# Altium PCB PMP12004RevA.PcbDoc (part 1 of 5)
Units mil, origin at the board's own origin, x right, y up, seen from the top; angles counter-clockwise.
Board outline 5500 x 4500 mil, 6 copper layers (Top Layer, GND, Signal Layer 1, Signal Layer 2, PWR Split, Bottom Layer), stack 0 mil thick; 355 components, 130 nets, 833 pads, 904 vias.
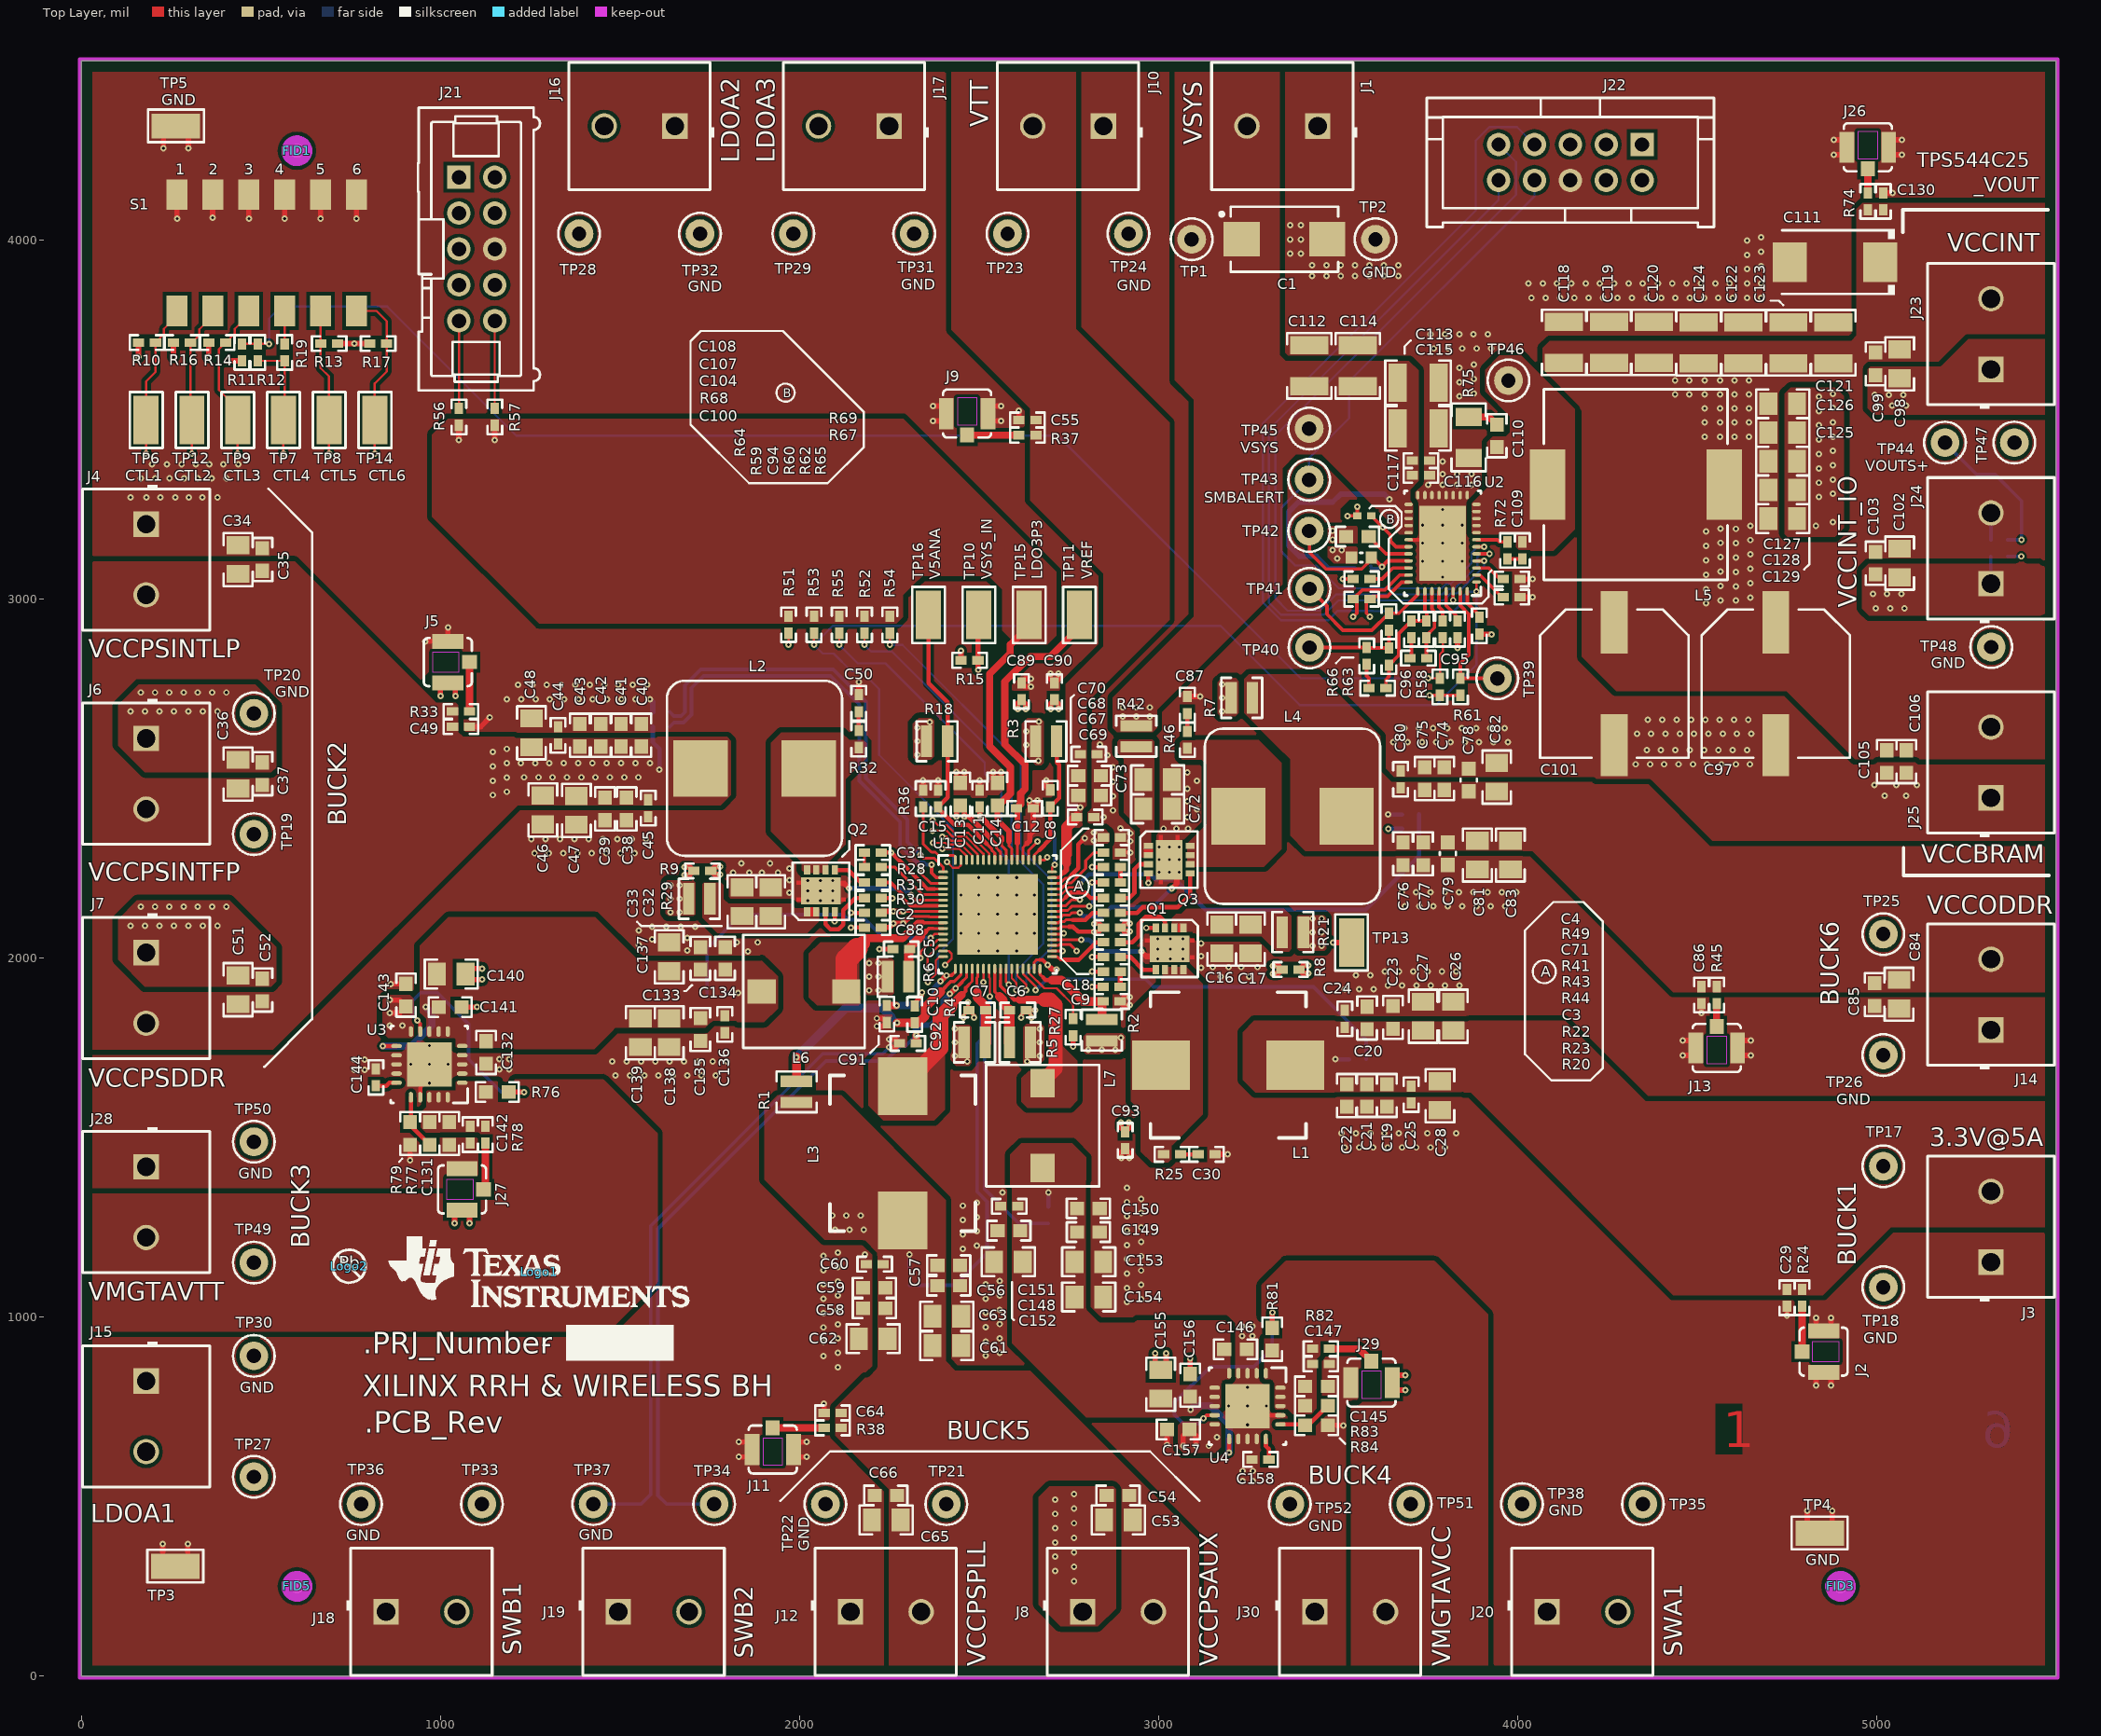
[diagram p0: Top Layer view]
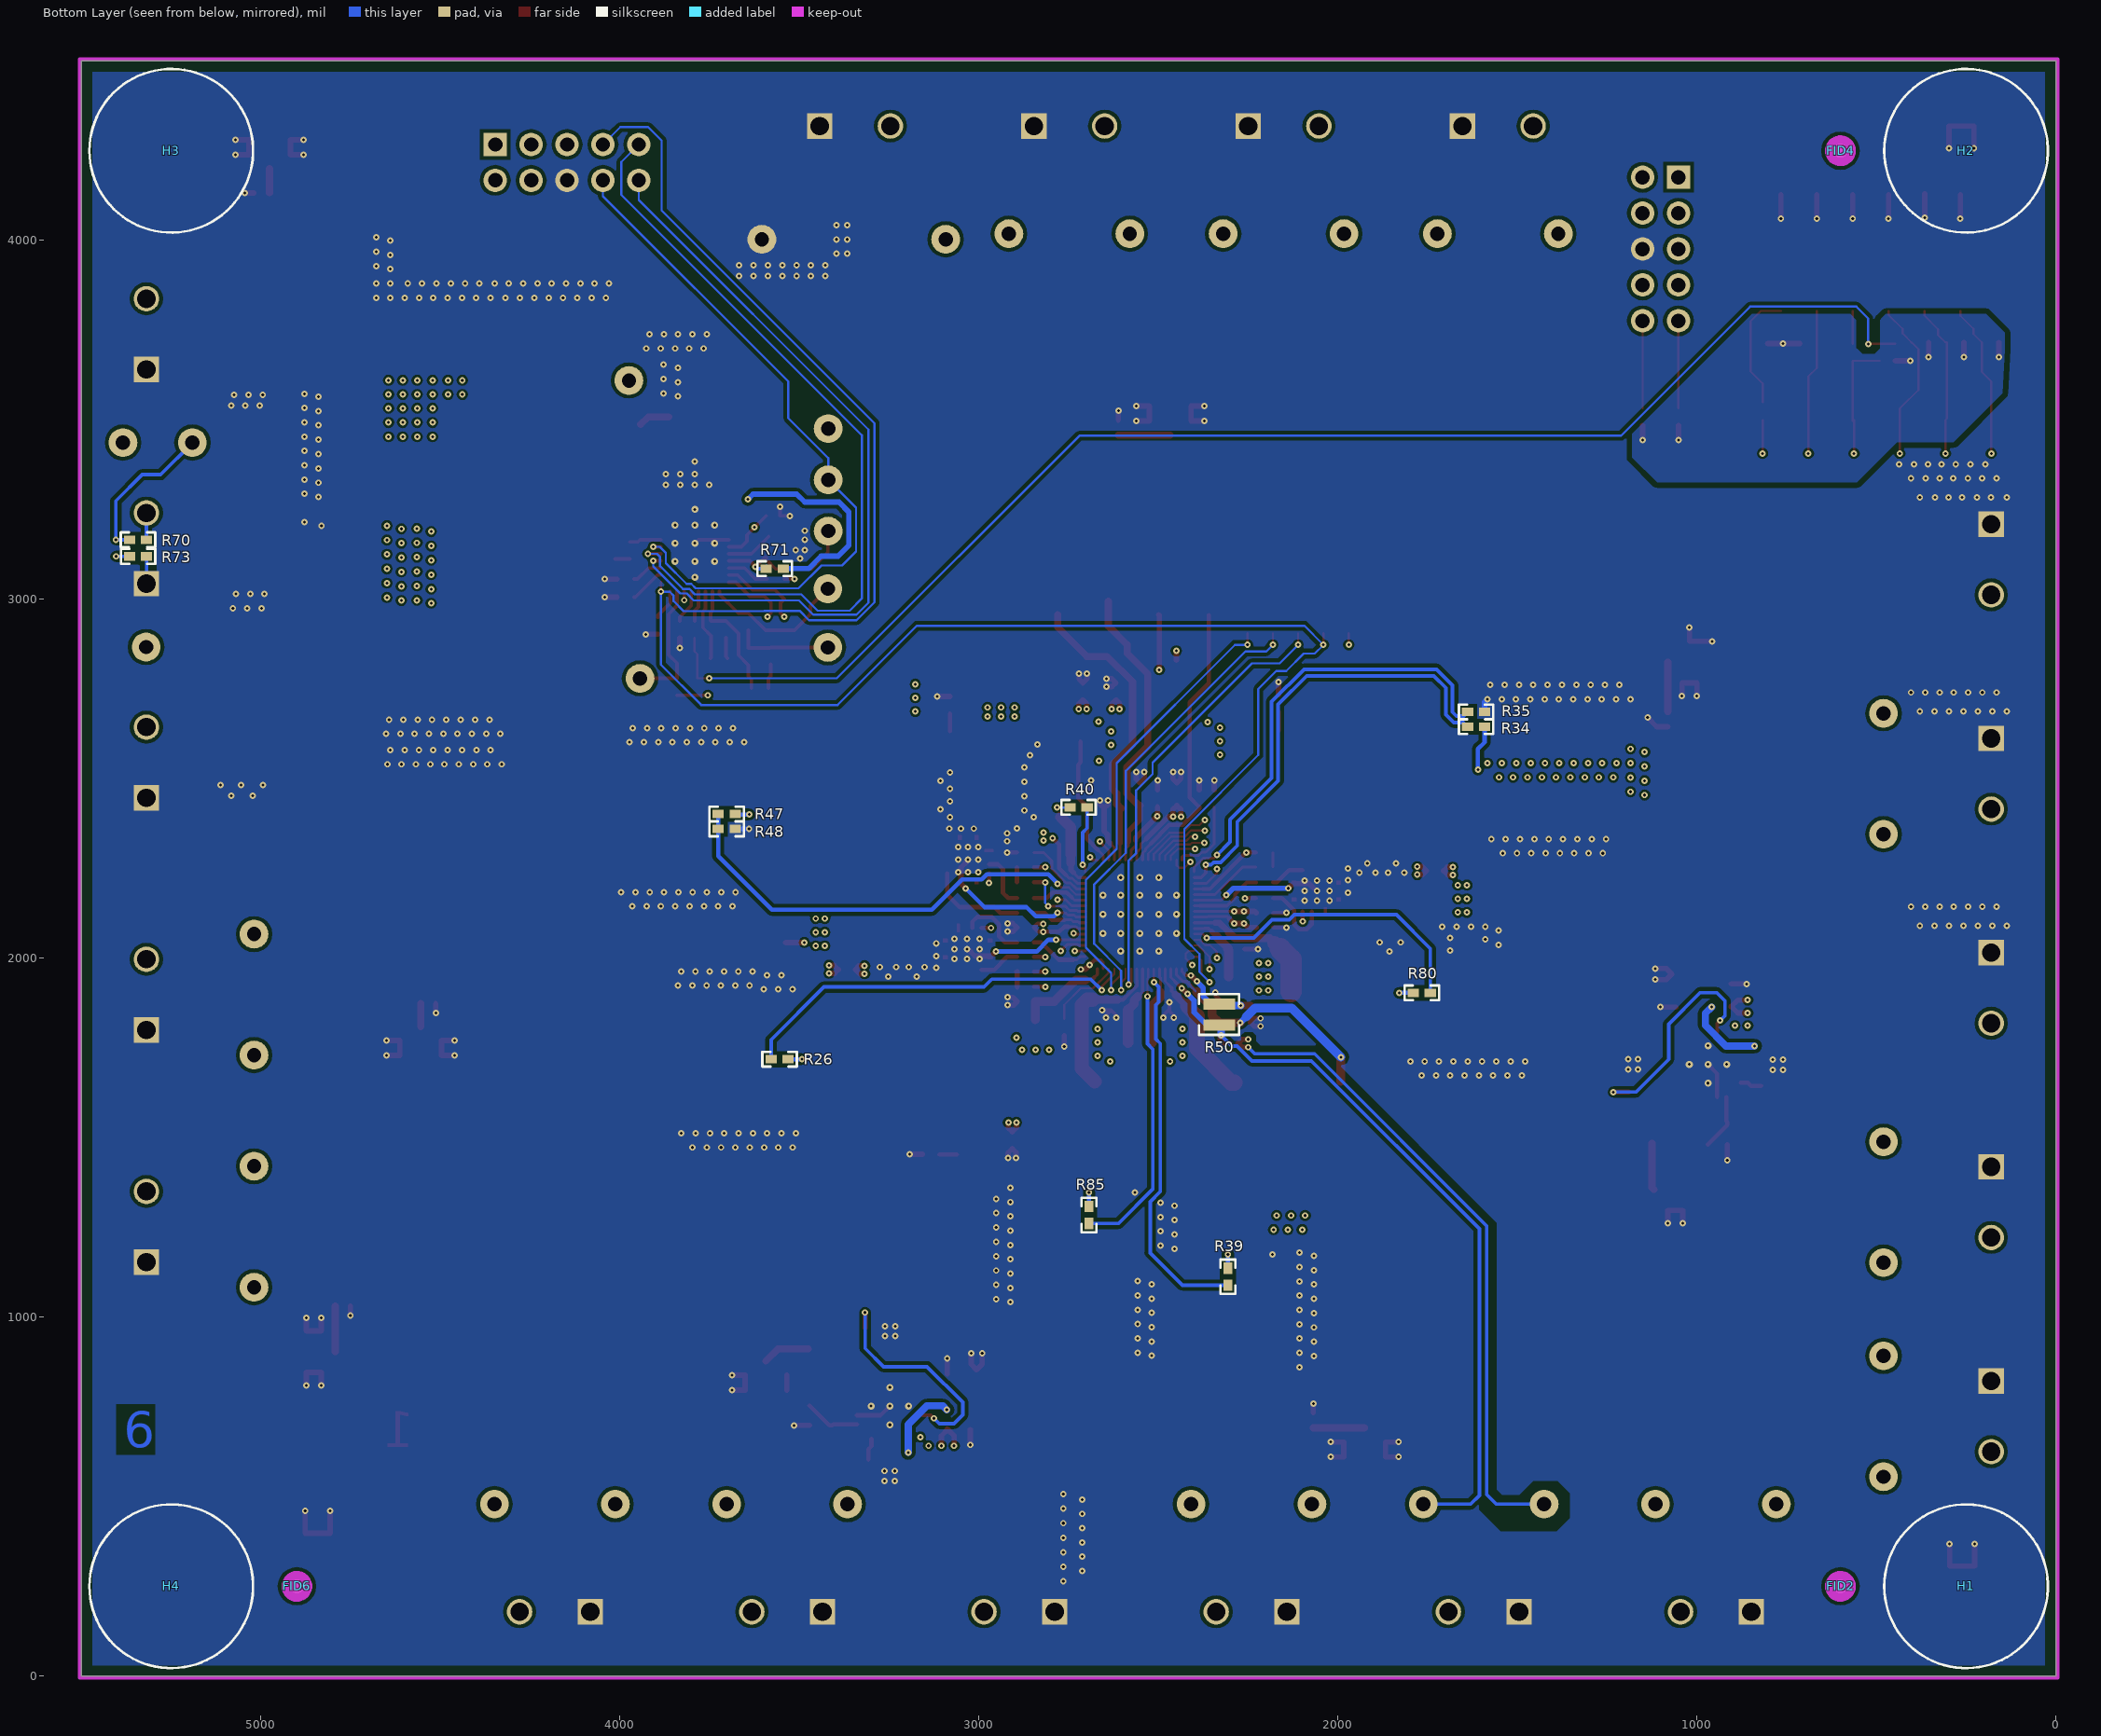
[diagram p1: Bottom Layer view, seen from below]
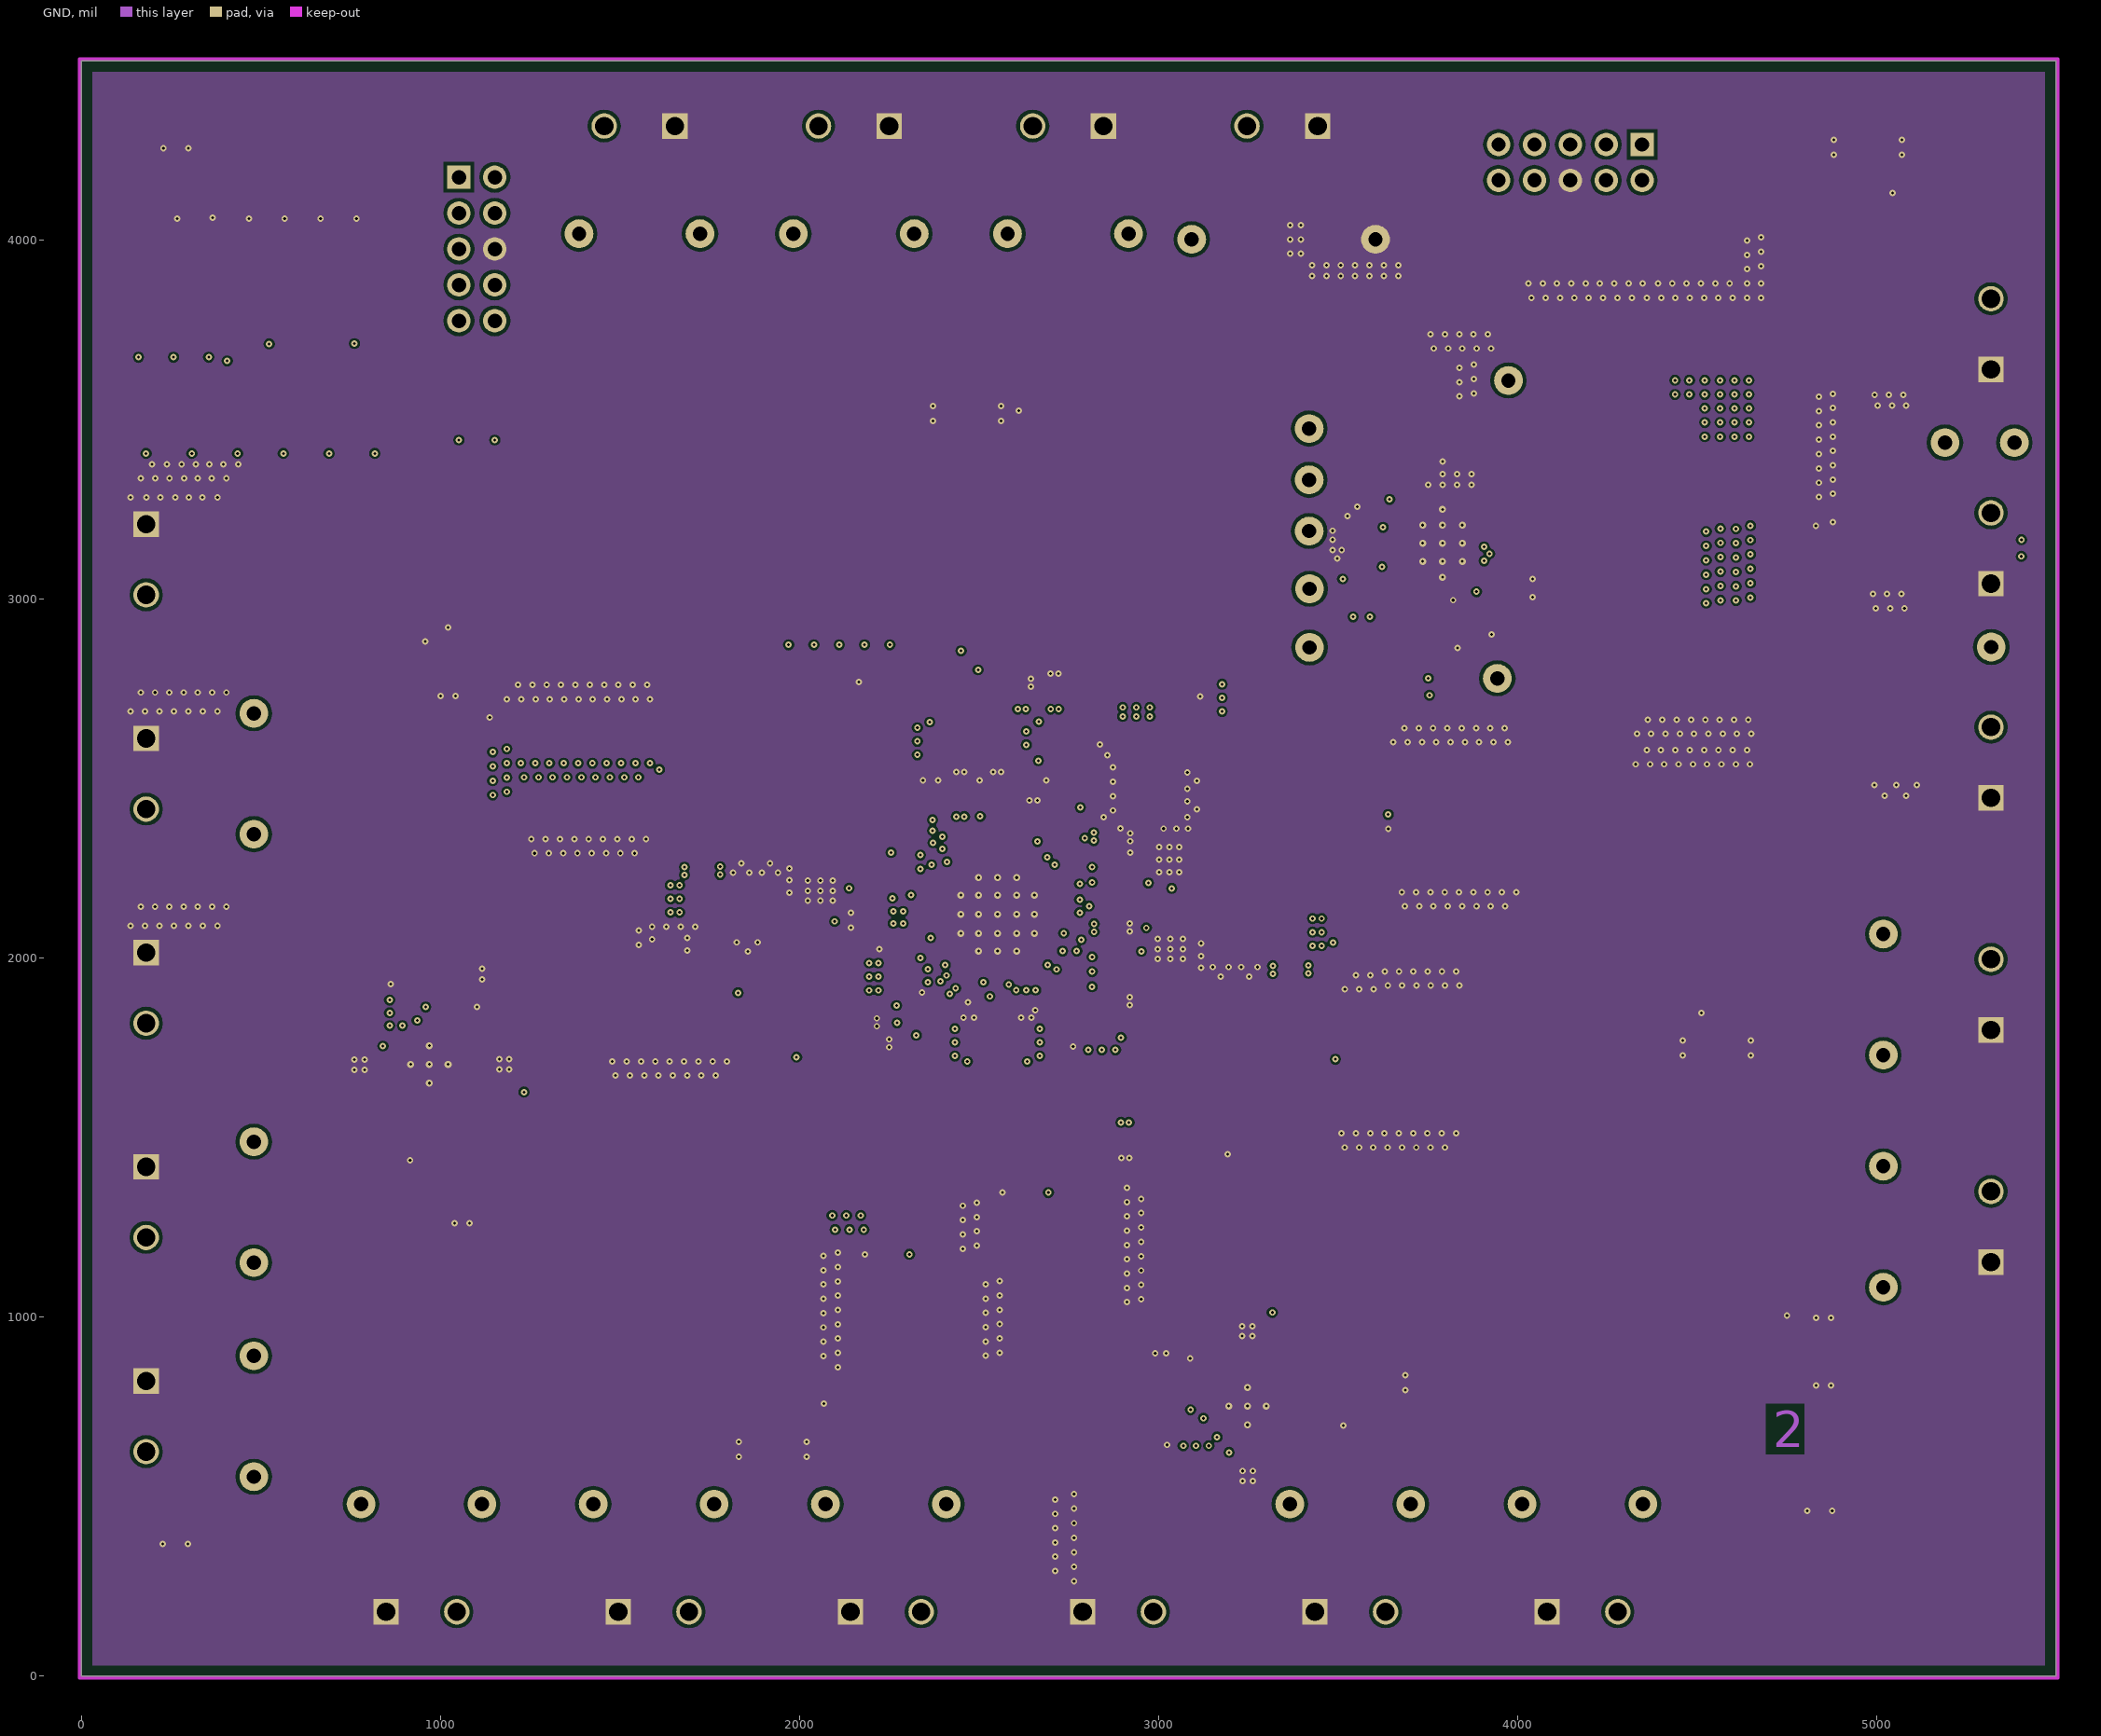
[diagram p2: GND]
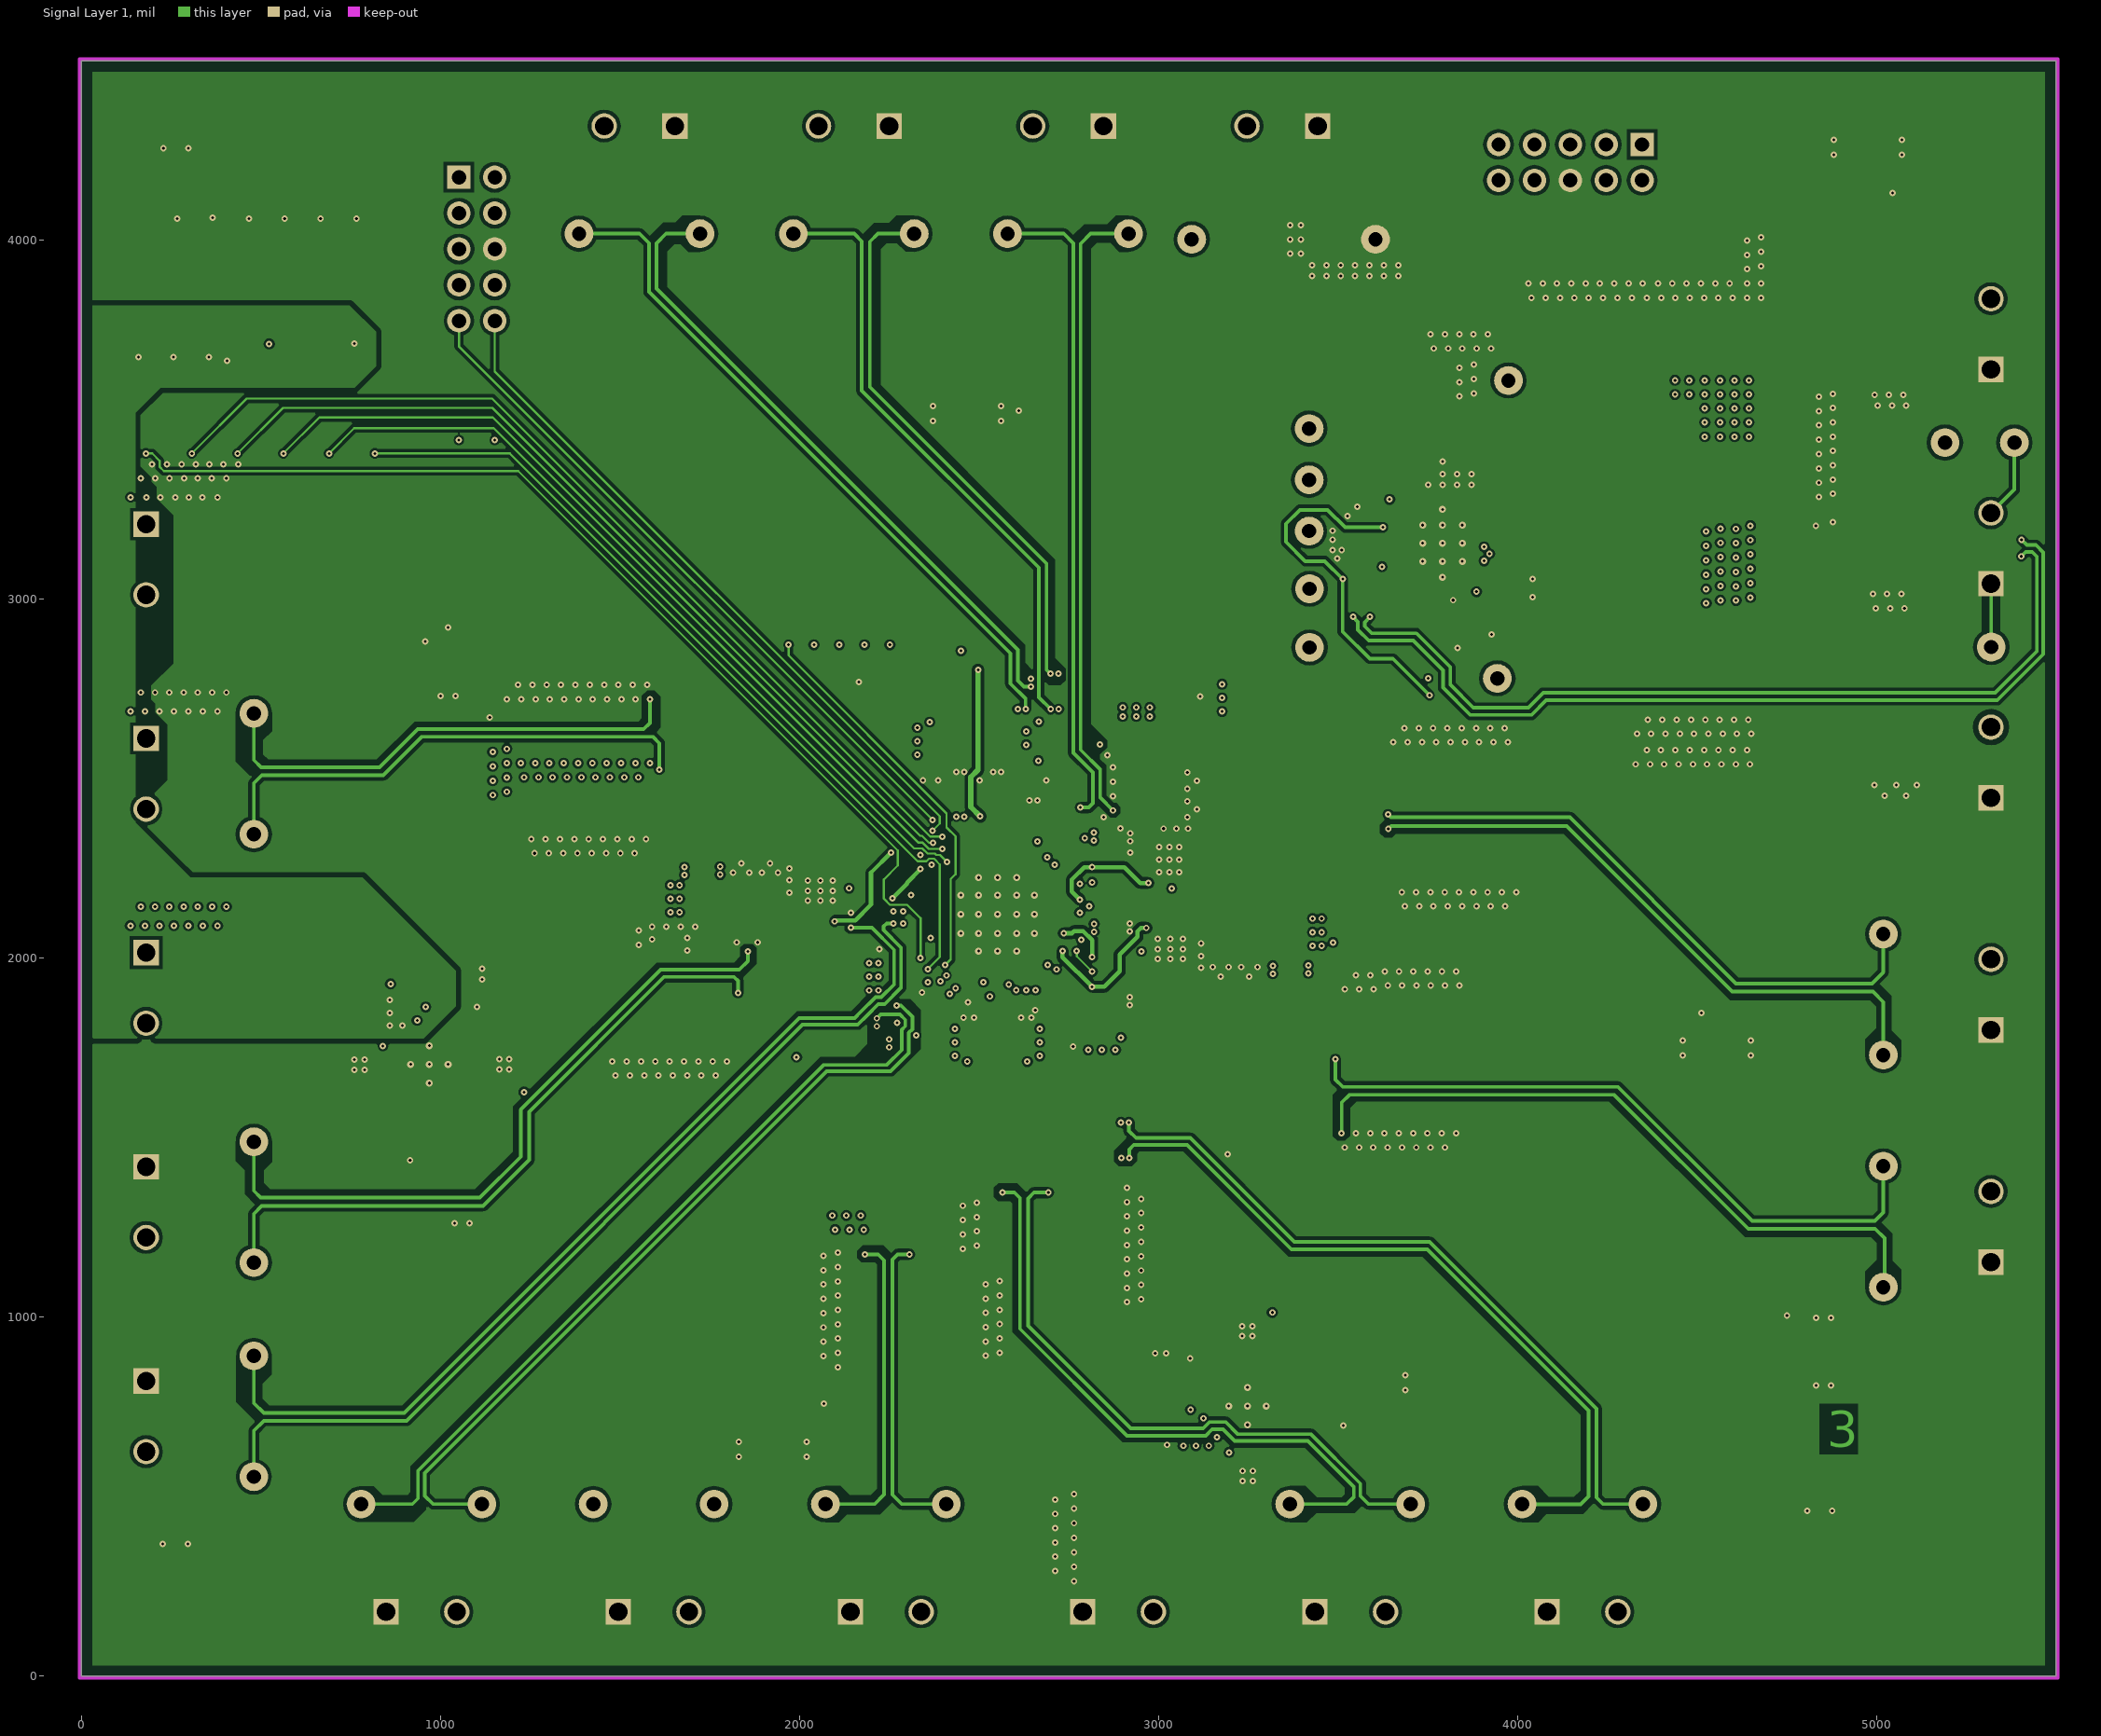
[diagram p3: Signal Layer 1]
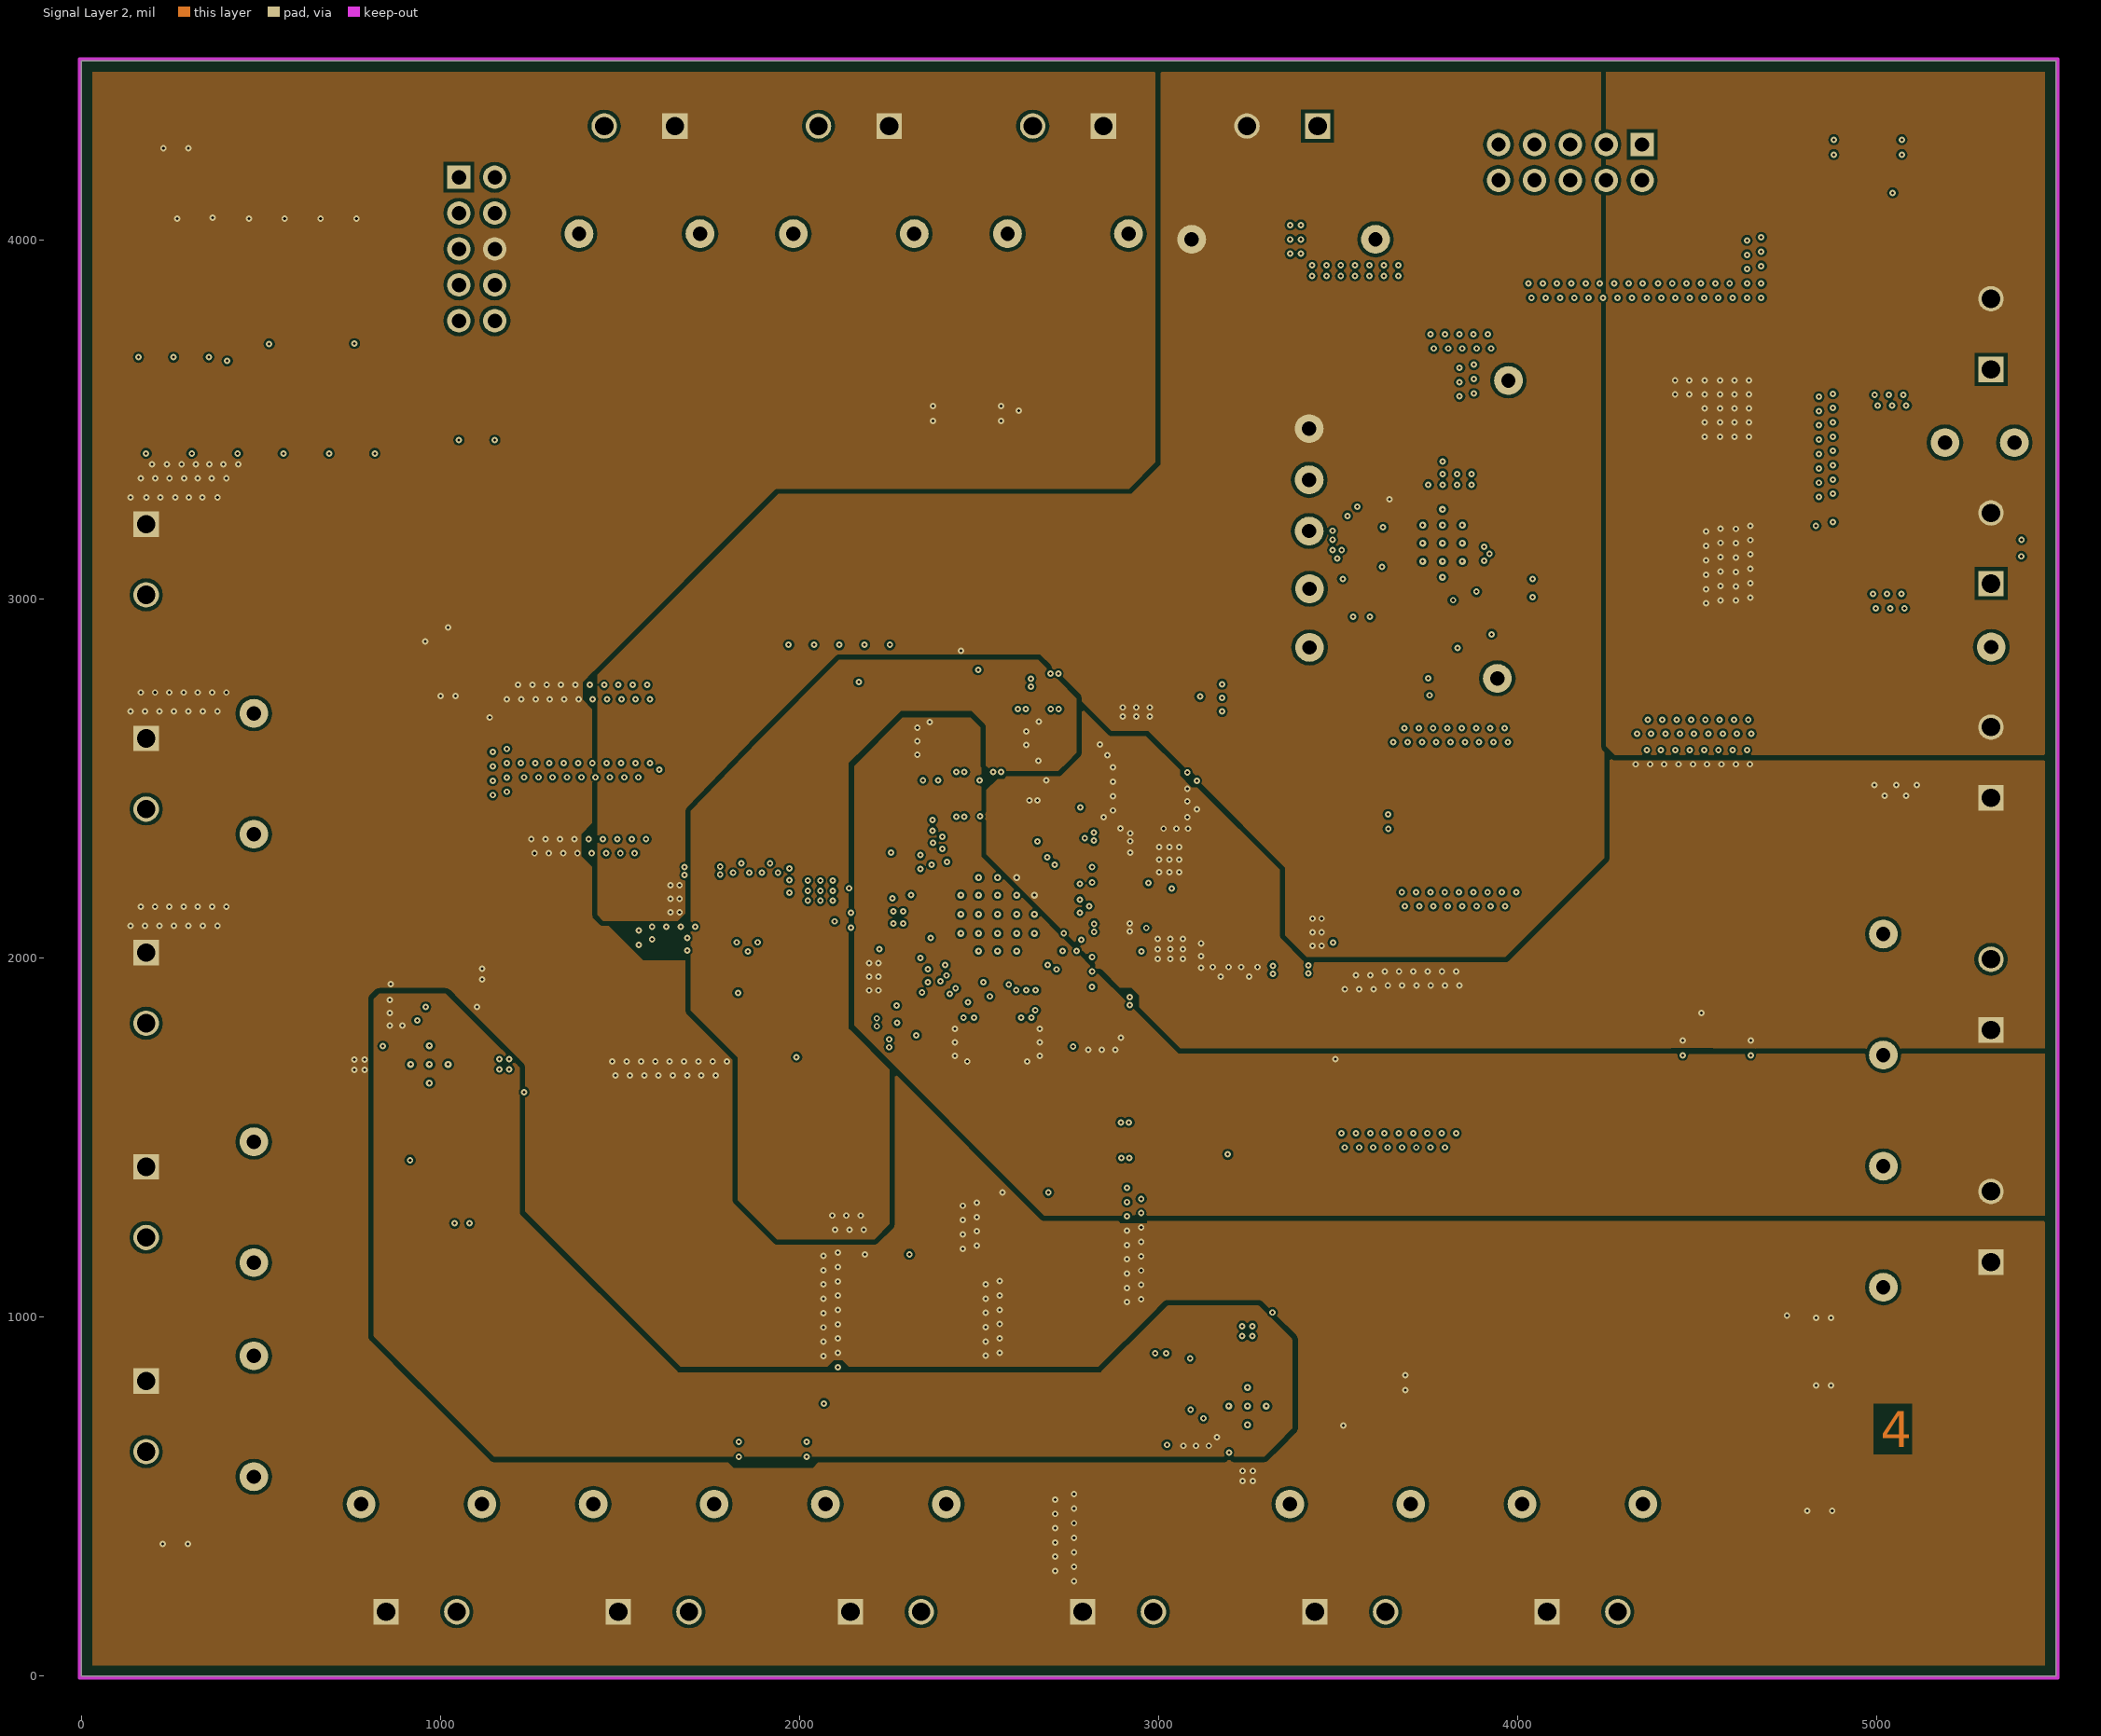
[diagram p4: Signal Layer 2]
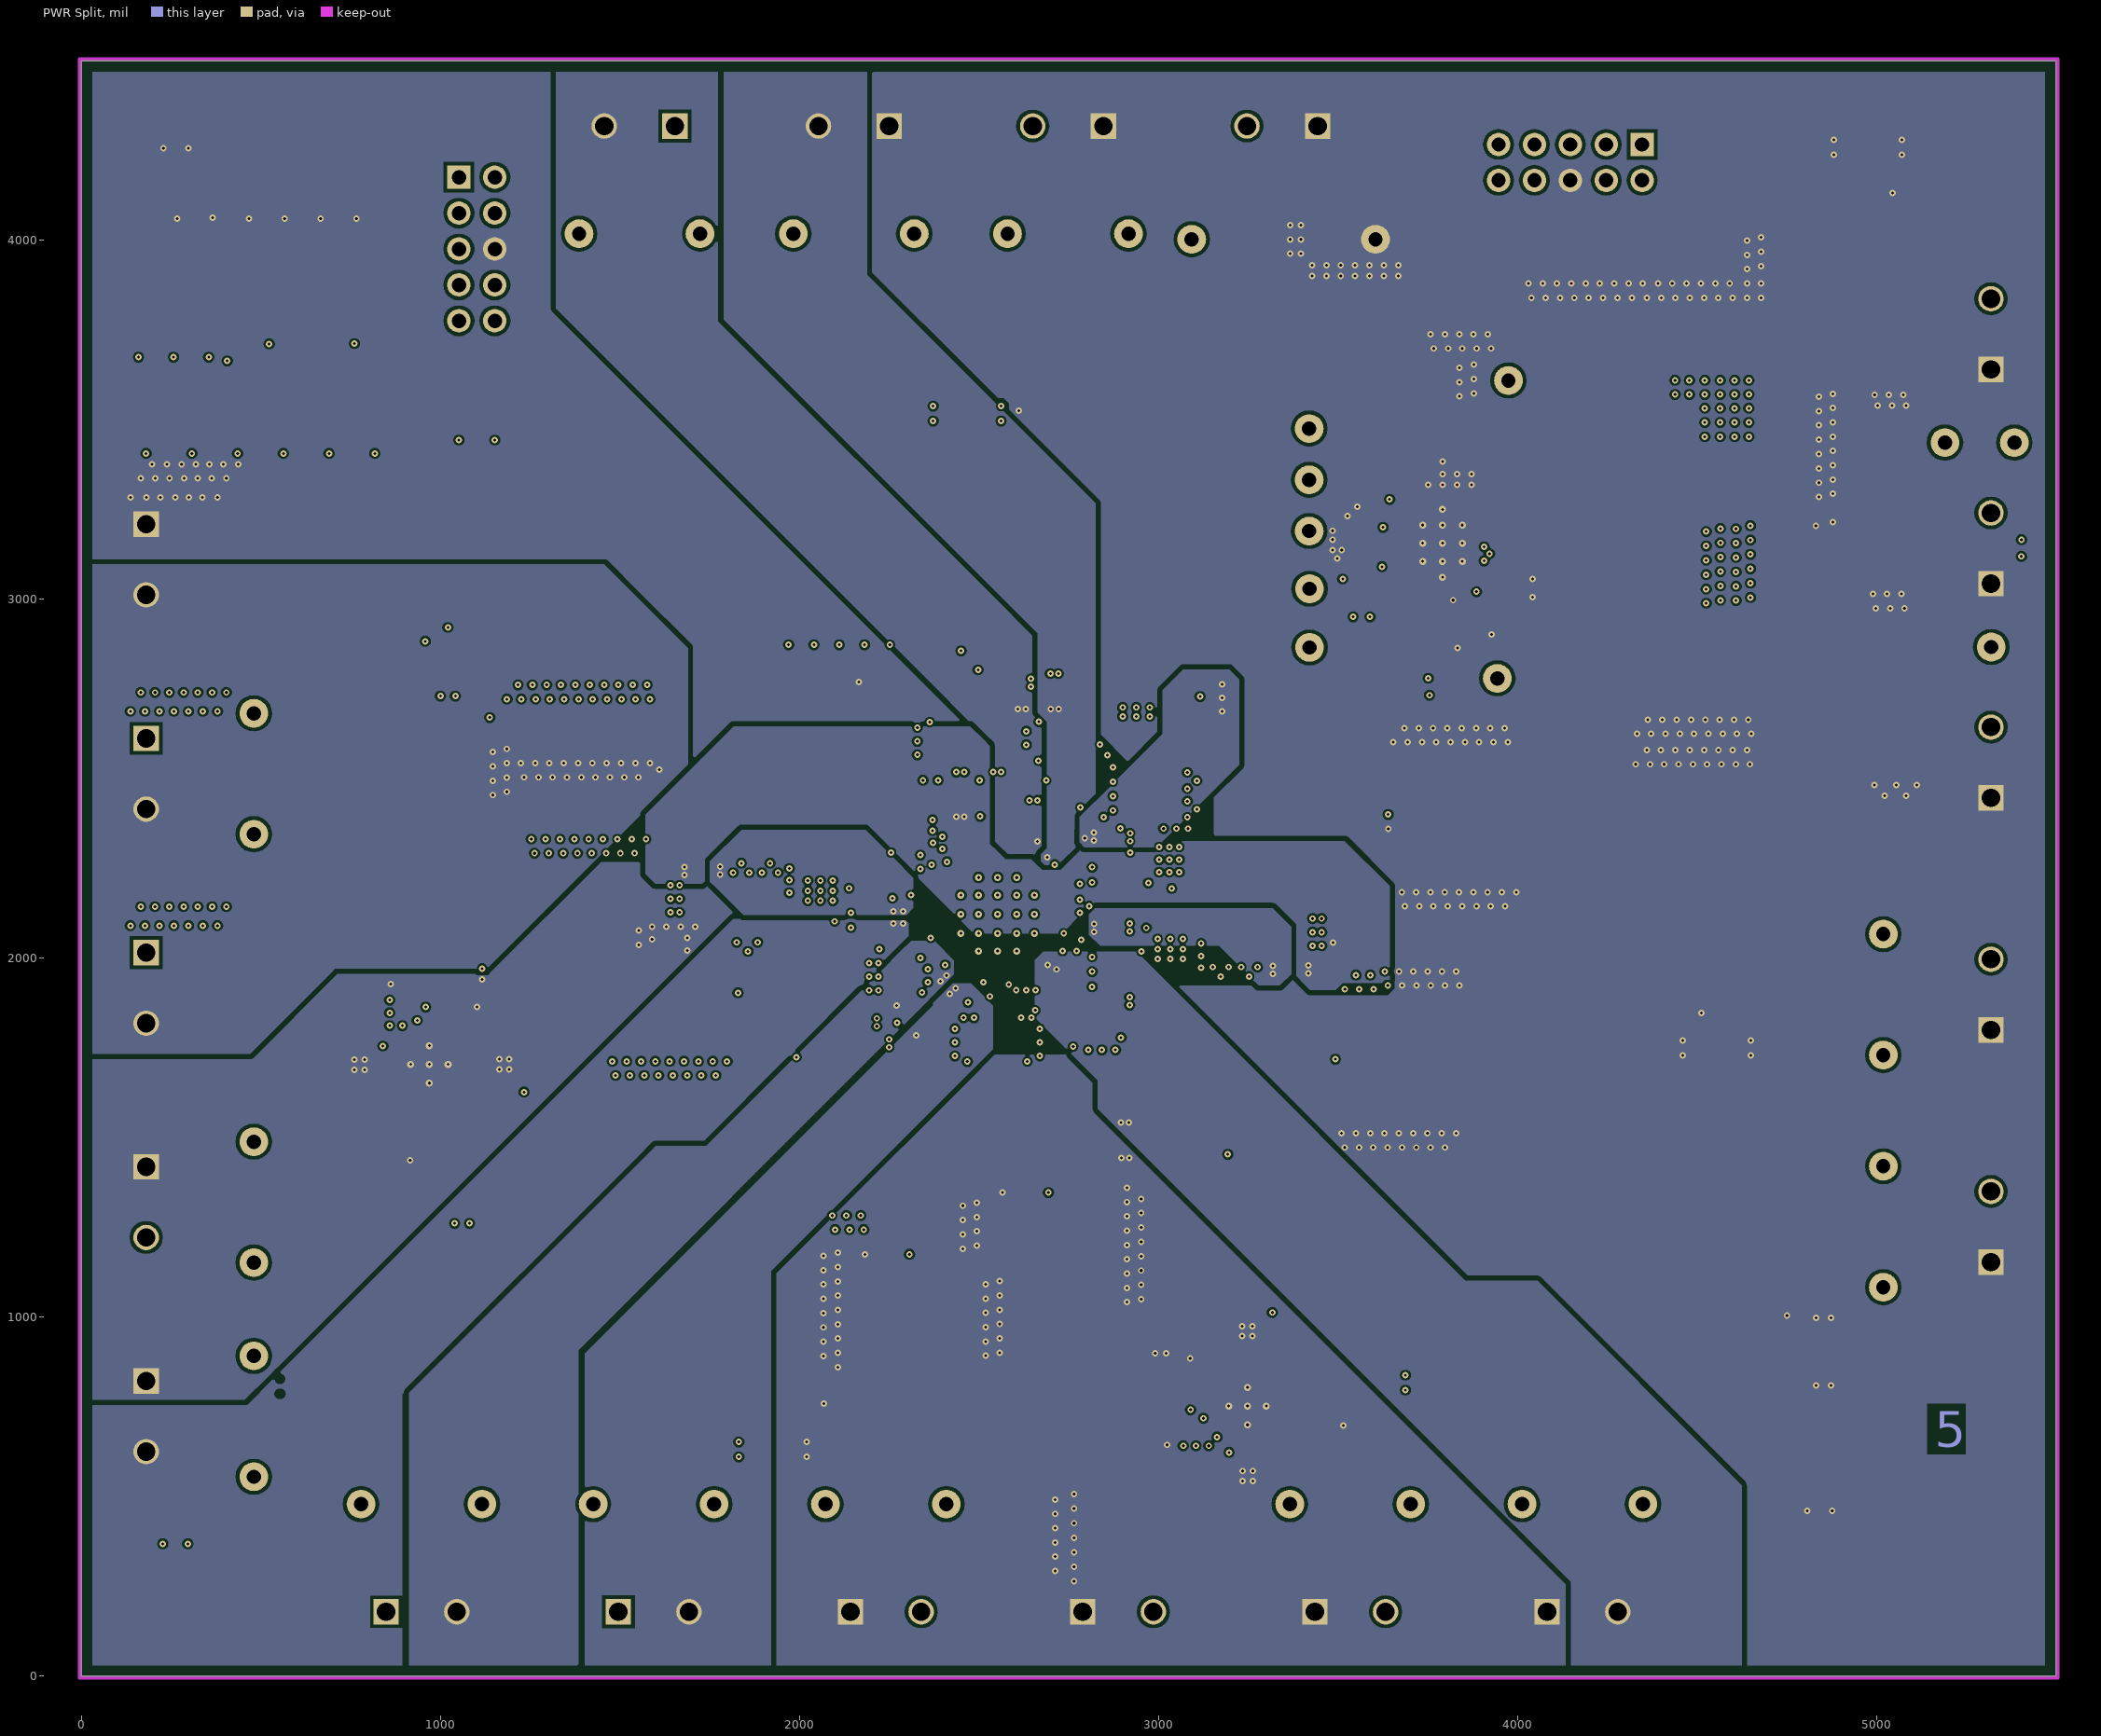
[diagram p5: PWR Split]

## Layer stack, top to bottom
Top Layer: signal copper (thickness not stored)
GND: signal copper (thickness not stored)
Signal Layer 1: signal copper (thickness not stored)
Signal Layer 2: signal copper (thickness not stored)
PWR Split: signal copper (thickness not stored)
Bottom Layer: signal copper (thickness not stored)

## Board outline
0,0 0,4500 5500,4500 5500,0

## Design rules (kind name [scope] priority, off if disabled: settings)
AcuteAngle [All] p1: minimum=4.50000000000000E+0001 checktracksonly=FALSE
AssemblyTestPointUsage [All] p1: valid=2
Clearance Clearance_Poly-Via [Inpoly vs isvia] p1: gap=6
Clearance Clearance_KO [OnLayer('Keep-Out Layer')] p2: gap=30
Clearance Clearance_Poly [InPolygon vs InPolygon] p3: gap=15
Clearance Clearance_Poly1 [InPolygon] p4: gap=10
Clearance [All] p5: gap=5
ComponentClearance ComponentClearance_1 [OnLayer('Top Layer') vs OnLayer('Bottom Layer')] p1: gap=0 collisioncheckmode=3 verticalgap=0 showdistances=FALSE
ComponentClearance [All] p2: gap=10 collisioncheckmode=3 verticalgap=10 showdistances=FALSE
DiffPairsRouting [All] p1: maxlimit=100 minlimit=10 mostfreqgap=10 toplayer_minwidth=15 toplayer_maxwidth=15 toplayer_prefwidth=15 midlayer1_minwidth=15 midlayer1_maxwidth=15 midlayer1_prefwidth=15 midlayer2_minwidth=15 midlayer2_maxwidth=15 midlayer2_prefwidth=15 midlayer3_minwidth=15 midlayer3_maxwidth=15 midlayer3_prefwidth=15 midlayer4_minwidth=15 midlayer4_maxwidth=15 midlayer4_prefwidth=15 bottomlayer_minwidth=15 bottomlayer_maxwidth=15 bottomlayer_prefwidth=15 maxuncoupledlength=1000
FabricationTestPointUsage TestPointUsage [All] p1: valid=2 allowmultiple=FALSE
FabricationTestpoint Testpoint [All] p1: side=3 testpointundercomponent=TRUE minsize=40 maxsize=100 preferedsize=60 minholesize=0 maxholesize=40 preferedholesize=32 testpointgrid=1 allowsidetop=TRUE allowsidebottom=TRUE usegrid=TRUE gridtolerance=0.01
FanoutControl Fanout_LCC [IsLCC] p1: bgadir=Out bgaviamode=Centered fanoutstyle=Auto fanoutdirection=Alternating viagrid=1 // Fanout_LCC (Default Rule)
FanoutControl Fanout_BGA [IsBGA] p2: bgadir=Out bgaviamode=Centered fanoutstyle=Auto fanoutdirection=Alternating viagrid=1 // Fanout_BGA (Default Rule)
FanoutControl Fanout_Default [All] p4: bgadir=Out bgaviamode=Centered fanoutstyle=Auto fanoutdirection=Alternating viagrid=1 // Fanout_Default (Default Rule)
FanoutControl Fanout_Small [(CompPinCount < 5)] p5: bgadir=Out bgaviamode=Centered fanoutstyle=Auto fanoutdirection=OutThenIn viagrid=1 // Fanout_Small (Default Rule)
HoleSize [All] p1: absolutevalues=TRUE maxlimit=251 minlimit=8 maxpercent=80.000 minpercent=20.000
MinimumAnnularRing MinimumAnnularRing_1 [ISVIA] p1: minimumring=4.9
MinimumAnnularRing [All] p2: minimumring=9
MinimumSolderMaskSliver MinimumSolderMaskSliver_1 [HasFootprint('TRANS_NexFET_Q3D')] p1: minsoldermaskwidth=3
MinimumSolderMaskSliver [All] p2: minsoldermaskwidth=3.94
PlaneConnect [All] p1: planeconnectstyle=Relief reliefexpansion=10 reliefentries=4 reliefconductorwidth=10 reliefairgap=10
PolygonConnect [All] p1: connectstyle=Direct reliefconductorwidth=10 reliefentries=4 polygonreliefangle="90 Angle" airgapwidth=10
RoutingVias ThermalPadVias [IsVia and InAnyComponent] p1: holewidth=7.87 width=19.68 viastyle="Through Hole" minholewidth=7.87 minwidth=19.68 maxholewidth=12.99 maxwidth=23.62
RoutingVias [All] p2: holewidth=16 width=34 viastyle="Through Hole" minholewidth=7.87 minwidth=18 maxholewidth=40 maxwidth=65
SilkToBoardRegionClearance [Not ((IsComment or IsDesignator) And (Hide <> 'False')) and not InRegion(1000,500,4000,800)] p1:
SilkToSilkClearance SilkToSilkClearance_Pb-FreeLogo [(HasFootprint('Pb-Free_Overlay_Medium') OR HasFootprint('Pb-Free_Overlay_Small')) vs (HasFootprint('Pb-Free_Overlay_Medium') OR HasFootprint('Pb-Free_Overlay_Small'))] p1: silktosilkclearance=0
SilkToSilkClearance [All] p2: silktosilkclearance=4
SilkToSolderMaskClearance [HasFootprint('TRANS_NexFET_Q3D')] p1: minsilkscreentomaskgap=1.8 clearancetoexposedcopper=TRUE
SilkToSolderMaskClearance "Silk to Solder Mask Opening" [All] p2: minsilkscreentomaskgap=4 clearancetoexposedcopper=FALSE
SolderMaskExpansion SolderMaskExpansion_1 [InPadClass('TH')] p1: expansion=2.5
SolderMaskExpansion [All] p2: expansion=0
Width [All] p1: maxlimit=100 minlimit=6 preferedwidth=10 checkconnectedcopper=TRUE
15 further rules are at their usual default settings.

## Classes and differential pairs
pad class TH: J1-1 J1-2 J3-1 J3-2 J4-1 J4-2 J6-1 J6-2 J7-1 J7-2 J8-1 J8-2 J10-1 J10-2 J12-1 J12-2 J14-1 J14-2 J15-1 J15-2 J16-1 J16-2 J17-1 J17-2 J18-1 J18-2 J19-1 J19-2 J20-1 J20-2 J21-1 J21-2 J21-3 J21-4 J21-5 J21-6 J21-7 J21-8 J21-9 J21-10 J22-1 J22-2 J22-3 J22-4 J22-5 J22-6 J22-7 J22-8 J22-9 J22-10 J23-1 J23-2 J24-1 J24-2 J25-1 J25-2 J28-1 J28-2 J30-1 J30-2 TP1-1 TP2-1 TP17-1 TP18-1 TP19-1 TP20-1 TP21-1 TP22-1 TP23-1 TP24-1 TP25-1 TP26-1 TP27-1 TP28-1 TP29-1 TP30-1 TP31-1 TP32-1 TP33-1 TP34-1 TP35-1 TP36-1 TP37-1 TP38-1 TP39-1 TP40-1 TP41-1 TP42-1 TP43-1 TP44-1 TP45-1 TP46-1 TP47-1 TP48-1 TP49-1 TP50-1 TP51-1 TP52-1
component class PMP12004RevA(860+C25)_sh1: C1 C2 C3 C4 C5 C6 C7 C8 C9 C10 C11 C12 C13 C14 C15 J1 R1 R2 R3 R4 R5 R6 R7 R8 R9 R10 R11 R12 R13 R14 R15 R16 R17 R18 R19 S1 TP1 TP2 TP3 TP4 TP5 TP6 TP7 TP8 TP9 TP10 TP11 TP12 TP13 TP14 TP15 TP16 U1
component class PMP12004RevA(860+C25)_sh2: C16 C17 C18 C19 C20 C21 C22 C23 C24 C25 C26 C27 C28 C29 C30 C31 C32 C33 C34 C35 C36 C37 C38 C39 C40 C41 C42 C43 C44 C45 C46 C47 C48 C49 C50 C51 C52 J2 J3 J4 J5 J6 J7 L1 L2 Q1 Q2 R20 R21 R22 R23 R24 R25 R26 R27 R28 R29 R30 R31 R32 R33 R34 R35 R36 TP17 TP18 TP19 TP20
component class PMP12004RevA(860+C25)_sh3: C131 C132 C133 C134 C135 C136 C137 C138 C139 C140 C141 C142 C143 C144 C145 C146 C147 C148 C149 C150 C151 C152 C153 C154 C155 C156 C157 C158 J27 J28 J29 J30 L6 L7 R76 R77 R78 R79 R80 R81 R82 R83 R84 R85 TP49 TP50 TP51 TP52 U3 U4
component class PMP12004RevA(860+C25)_sh4: C53 C54 C55 C56 C57 C58 C59 C60 C61 C62 C63 C64 C65 C66 C67 C68 C69 C70 C71 C72 C73 C74 C75 C76 C77 C78 C79 C80 C81 C82 C83 C84 C85 C86 C87 J8 J9 J10 J11 J12 J13 J14 L3 L4 Q3 R37 R38 R39 R40 R41 R42 R43 R44 R45 R46 R47 R48 R49 TP21 TP22 TP23 TP24 TP25 TP26
component class PMP12004RevA(860+C25)_sh5: C88 C89 C90 C91 C92 C93 J15 J16 J17 J18 J19 J20 J21 R50 R51 R52 R53 R54 R55 R56 R57 TP27 TP28 TP29 TP30 TP31 TP32 TP33 TP34 TP35 TP36 TP37 TP38
component class PMP12004RevA(860+C25)_sh6: C94 C95 C96 C97 C98 C99 C100 C101 C102 C103 C104 C105 C106 C107 C108 C109 C110 C111 C112 C113 C114 C115 C116 C117 C118 C119 C120 C121 C122 C123 C124 C125 C126 C127 C128 C129 C130 J22 J23 J24 J25 J26 L5 R58 R59 R60 R61 R62 R63 R64 R65 R66 R67 R68 R69 R70 R71 R72 R73 R74 R75 TP39 TP40 TP41 TP42 TP43 TP44 TP45 TP46 TP47 TP48 U2
component class AssemblyNote: ZZ1 ZZ2 ZZ3
component class FiducialMark: FID1 FID2 FID3 FID4 FID5 FID6
component class Logo: Logo1
component class PMP12004RevA(860+C25)_Hardware: FID1 FID2 FID3 FID4 FID5 FID6 H1 H2 H3 H4 Logo1 Logo2 ZZ1 ZZ2 ZZ3

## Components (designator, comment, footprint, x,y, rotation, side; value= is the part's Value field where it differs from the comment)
C1 "T495X476K035ATE300" 7343-43 3350.96,4003.5 r0 top locked
C2 "CL05A225KQ5NNNC" 0402 2204.42,2126.59 r180 top locked
C3 "CL05A225KQ5NNNC" 0402 2870.42,2085.59 r0 top locked
C4 "CL05A106MP5NUNC" 0402 2870.42,2336.59 r0 top locked
C5 "CL05A106MP5NUNC" 0402 2283.8,2025.59 r180 top locked
C6 "CL05A106MP5NUNC" 0402 2608.42,1855.59 r0 top locked
C7 "CL05A106MP5NUNC" 0402 2495.42,1855.59 r180 top locked
C8 "GRM155R60J475ME47D" 0402 2698.8,2445.59 r90 top locked
C9 "GRM155R61A105KE15D" 0402 2870.04,1879.59 r0 top locked
C10 "GRM155R61A105KE15D" 0402 2320.92,1843.59 r90 top locked
C11 "GRM155R6YA105KE11D" 0402 2502.42,2445.22 r90 top locked
C12 "GRM155R61A104KA01D" 0402 2627.8,2417.59 r0 top locked
C13 "GRM188R61A475ME15" 0603 2448.42,2457.09 r90 top locked
C14 "GRM188R61A475ME15" 0603 2551.42,2457.09 r90 top locked
C15 "GRM155R61A105KE15D" 0402 2386.42,2445.22 r90 top locked
C16 "GRM21BR61E226ME44" 0805_HV 3176.42,2053.59 r270 top locked
C17 "GRM21BR61E226ME44" 0805_HV 3256.42,2053.59 r270 top locked
C18 "GRM155R61A104KA01D" 0402 2870.04,1920.59 r0 top locked
C19 "GRM188R60J226MEA0J" 0603 3636.42,1617.59 r270 top locked
C20 "GRM188R60J226MEA0J" 0603 3581.42,1833.61 r90 top locked
C21 "GRM188R60J226MEA0J" 0603 3580.42,1617.59 r270 top locked
C22 "GRM188R60J226MEA0J" 0603 3524.42,1617.58 r270 top locked
C23 "GRM188R60J226MEA0J" 0603 3653.42,1835.09 r90 top locked
C24 "GRM155R61A104KA01D" 0402 3519.42,1831.22 r90 top locked
C25 "GRM155R61A104KA01D" 0402 3704,1620 r270 top locked
C26 "GRM21BR61A476ME15" 0805_HV 3821.42,1838.59 r90 top locked
C27 "GRM21BR61A476ME15" 0805_HV 3737.42,1838.59 r90 top locked
C28 "GRM21BR61A476ME15" 0805_HV 3784,1617 r270 top locked
C29 "GRM155R61E104KA87D" 0402 4751.01,1053.89 r270 top
C30 "GRM155R71E682KA01D" 0402 3134.04,1453.59 r0 top locked
C31 "GRM155R61A104KA01D" 0402 2204.42,2294.59 r180 top locked
C32 "GRM21BR61E226ME44" 0805_HV 1919.8,2157.59 r90 top locked
C33 "GRM21BR61E226ME44" 0805_HV 1839.8,2157.59 r90 top locked
C34 "GRM21BR60G107ME15L" 0805_HV 436,3111 r90 top locked
C35 "GRM188R60J475ME19D" 0603 504,3111 r90 top locked
C36 "GRM21BR60G107ME15L" 0805_HV 436,2513.15 r90 top locked
C37 "GRM188R60J475ME19D" 0603 504,2514.15 r90 top locked
C38 "GRM188R60J226MEA0J" 0603 1518.42,2416.22 r270 top locked
C39 "GRM188R60J226MEA0J" 0603 1458.35,2416.22 r270 top locked
C40 "GRM188R60J226MEA0J" 0603 1559.42,2621.22 r90 top locked
C41 "GRM188R60J226MEA0J" 0603 1503,2621.22 r90 top locked
C42 "GRM188R60J226MEA0J" 0603 1446.21,2621.22 r90 top locked
C43 "GRM188R60J226MEA0J" 0603 1388.21,2621.22 r90 top locked
C44 "GRM155R61A104KA01D" 0402 1327.21,2621.04 r90 top locked
C45 "GRM155R61A104KA01D" 0402 1578.42,2418.22 r270 top locked
C46 "GRM21BR61A476ME15" 0805_HV 1285.04,2413.22 r270 top locked
C47 "GRM21BR61A476ME15" 0805_HV 1378.42,2412.22 r270 top locked
C48 "GRM21BR61A476ME15" 0805_HV 1253.4,2628.13 r90 top locked
C49 "GRM155R61E104KA87D" 0402 1057.01,2645.31 r0 top locked
C50 "GRM155R71E682KA01D" 0402 2165.22,2710.74 r90 top locked
C51 "GRM21BR60G107ME15L" 0805_HV 436,1912.3 r90 top locked
C52 "GRM188R60J475ME19D" 0603 504,1911.3 r90 top locked
C53 "GRM21BR60G107ME15L" 0805_HV 2888.55,435 r180 top locked
C54 "GRM188R60J475ME19D" 0603 2887.55,503 r180 top locked
C55 "GRM155R61E104KA87D" 0402 2635.09,3499.8 r180 top locked
C56 "C1608X5R0J226M080AC" 0603 2415.91,1087.59 r0 top locked
C57 "C1608X5R0J226M080AC" 0603 2415.91,1144.59 r0 top locked
C58 "C1608X5R0J226M080AC" 0603 2208.42,1024.59 r180 top locked
C59 "GRM188R60J226MEA0J" 0603 2208.42,1081.59 r180 top locked
C60 "GRM155R61A104KA01D" 0402 2209.8,1147.59 r180 top locked
C61 "GRM21BR61A476ME15" 0805_HV 2410.42,920.59 r0 top locked
C62 "GRM21BR61A476ME15" 0805_HV 2205.42,939.59 r180 top locked
C63 "GRM21BR61A476ME15" 0805_HV 2410.42,1002.59 r0 top locked
C64 "GRM155R61E104KA87D" 0402 2092.23,733.53 r180 top locked
C65 "GRM21BR60G107ME15L" 0805_HV 2241.7,435 r180 top locked
C66 "GRM188R60J475ME19D" 0603 2240.7,503 r180 top locked
C67 "GRM188R60J226MEA0J" 0603 2808.04,2453.59 r0 top locked
C68 "GRM188R60J226MEA0J" 0603 2808.04,2508.59 r0 top locked
C69 "GRM155R61A104KA01D" 0402 2796.04,2393.59 r0 top locked
C70 "GRM155R61A104KA01D" 0402 2805.66,2568.59 r0 top locked
C71 "GRM155R61A104KA01D" 0402 2870.42,2253.59 r0 top locked
C72 "GRM21BR61E226ME44" 0805_HV 2997.83,2416.33 r0 top locked
C73 "GRM21BR61E226ME44" 0805_HV 2997.83,2497.33 r0 top locked
C74 "GRM188R60J226MEA0J" 0603 3796.42,2500.47 r90 top locked
C75 "GRM188R60J226MEA0J" 0603 3741.42,2500.47 r90 top locked
C76 "GRM188R60J226MEA0J" 0603 3681.42,2291.1 r270 top locked
C77 "GRM188R60J226MEA0J" 0603 3737.42,2291.1 r270 top locked
C78 "ZRB18AR60G476ME01" 0603_120 3864.42,2496.59 r90 top locked
C79 "ZRB18AR60G476ME01" 0603_120 3806.42,2291.59 r270 top locked
C80 "GRM155R61A104KA01D" 0402 3674.42,2498.59 r90 top locked
C81 "GRM21BR61A476ME15" 0805_HV 3888.42,2287.59 r270 top locked
C82 "GRM21BR61A476ME15" 0805_HV 3942.42,2504.59 r90 top locked
C83 "GRM21BR61A476ME15" 0805_HV 3980.42,2287.59 r270 top locked
C84 "GRM21BR60G107ME15L" 0805_HV 5063.33,1899.77 r270 top locked
C85 "GRM188R60J475ME19D" 0603 4995.33,1898.77 r270 top locked
C86 "GRM155R61E104KA87D" 0402 4513.05,1897.44 r270 top locked
C87 "GRM155R71E682KA01D" 0402 3080.48,2705.52 r90 top locked
C88 "GRM155R60J475ME47D" 0402 2204.42,2085.59 r180 top locked
C89 "GRM155R60J475ME47D" 0402 2618.42,2743.59 r90 top locked
C90 "GRM155R60J475ME47D" 0402 2710.42,2743.59 r90 top locked
C91 "GRM155R61A104KA01D" 0402 2243.42,1844.59 r270 top locked
C92 "GRM155R61A104KA01D" 0402 2301.8,1762.59 r180 top locked
C93 "GRM155R61A104KA01D" 0402 2907.42,1492.97 r270 top locked
C94 "GRM1535C1H101JDD5D" 0402 3746.23,2916.38 r270 top locked
C95 "C1005X7R1H222K" 0402 3724.23,2836.38 r0 top locked
C96 "GRM155R71H272KA01D" 0402 3610.23,2752.38 r180 top locked
C97 "4SVP680M" SM_RADIAL_10AMM 4720,2765 r270 top locked
C98 "GRM21BR60G107ME15L" 0805_HV 5064.93,3656.28 r270 top locked
C99 "GRM188R60J475ME19D" 0603 4997.72,3656.23 r270 top locked
C100 "GRM155R71H331KA01D" 0402 3566,3000.52 r0 top locked
C101 "4SVP680M" SM_RADIAL_10AMM 4270,2765 r270 top locked
C102 "GRM21BR60G107ME15L" 0805_HV 5064.93,3101.06 r270 top locked
C103 "GRM188R60J475ME19D" 0603 4997.72,3100.95 r270 top locked
C104 "GRM188R71E105KA12D" 0603L 3565.23,3116.92 r180 top locked
C105 "GRM188R60J476M" 0603 5028.8,2547.98 r270 top locked
C106 "GRM188R60J475KE19D" 0603 5083.8,2547.98 r270 top locked
C107 "GRM185C81A475ME11D" 0603 3554.23,3174.92 r180 top locked
C108 "GRM155C80J225KE95D" 0402L 3573.28,3232.68 r180 top locked
C109 "C1005X7R1H104M" 0402 4014.23,3136.38 r90 top locked
C110 "06031C102JAT2A" 0603 3942.67,3455.67 r90 top locked
C111 "EEFSX0E471XE" SP-Cap_Standard 4885,3940 r180 top locked
C112 "GRM32EC81E226KE15L" 1210 3420,3650.97 r90 top locked
C113 "GRM32EC81E226KE15L" 1210 3723.31,3603.74 r0 top locked
C114 "GRM32EC81E226KE15L" 1210 3555,3650.97 r90 top locked
C115 "GRM32EC81E226KE15L" 1210 3723.31,3476.38 r0 top locked
C116 "GRM155R71E682KA01D" 0402 3731.31,3345.74 r0 top locked
C117 "GRM155R71E682KA01D" 0402 3731.31,3386.38 r0 top locked
C118 "GRM32EC80J107ME20L" 1210 4130,3715.97 r90 top locked
C119 "GRM32EC80J107ME20L" 1210 4255,3715.97 r90 top locked
C120 "GRM32EC80J107ME20L" 1210 4380,3715.97 r90 top locked
C121 "GRM32EC80J107ME20L" 1210 4880,3715 r90 top locked
C122 "GRM32EC80J107ME20L" 1210 4630,3715 r90 top locked
C123 "GRM32EC80J107ME20L" 1210 4755,3715 r90 top locked
C124 "GRM32EC80J107ME20L" 1210 4505,3715 r90 top locked
C125 "GRM21BC80G226ME39L" 0805_HV 4739.03,3465 r0 top locked
C126 "GRM21BC80G226ME39L" 0805_HV 4739.03,3545 r0 top locked
C127 "GRM21BR61A476ME15" 0805_HV 4739.03,3385 r0 top locked
C128 "GRM21BR61A476ME15" 0805_HV 4739.03,3305 r0 top locked
C129 "GRM21BR61A476ME15" 0805_HV 4739.03,3225 r0 top locked
C130 "GRM155R61E104KA87D" 0402 5019.68,4108.98 r90 top locked
C131 "GRM188R61A335KE15D" 0603 1024.65,1511.84 r270 top locked
C132 "GRM188R61A335KE15D" 0603 1126.96,1737.54 r270 top locked
C133 "GRM188R60J226MEA0J" 0603 1724.07,1999.59 r90 top locked
C134 "GRM188R60J226MEA0J" 0603 1792.92,1999.59 r90 top locked
C135 "GRM188R60J226MEA0J" 0603 1724,1801.5 r270 top locked
C136 "GRM155R61A104KA01D" 0402 1792,1816 r270 top locked
C137 "GRM21BR61A476ME15" 0805_HV 1637,2004 r90 top locked
C138 "GRM21BR61A476ME15" 0805_HV 1637,1792.43 r270 top locked
C139 "GRM21BR61A476ME15" 0805_HV 1556.88,1792.43 r270 top locked
C140 "GRM21BR60G107ME15L" 0805_HV 1029.96,1956.03 r0 top locked
C141 "GRM188R60J475ME19D" 0603 1026.96,1864.03 r0 top locked
C142 "GRM155R61E104KA87D" 0402 1082.71,1508.45 r270 top
C143 "GRM188R61A335KE15D" 0603 903.96,1897.03 r90 top locked
C144 "GRM155R60J102KA01D" 0402 819.96,1668.03 r90 top locked
C145 "GRM188R61A335KE15D" 0603 3440.37,807.19 r0 top locked
C146 "GRM188R61A335KE15D" 0603 3214.86,910.19 r0 top locked
C147 "GRM155R61E104KA87D" 0402 3452.49,869.66 r0 top
C148 "C1608X5R0J226M080AC" 0603 2583.5,1241 r180 top locked
C149 "C1608X5R0J226M080AC" 0603 2805,1236.93 r0 top locked
C150 "C1608X5R0J226M080AC" 0603 2805,1303 r0 top locked
C151 "GRM155R61A104KA01D" 0402 2584.38,1309 r180 top locked
C152 "GRM21BR61A476ME15" 0805_HV 2582,1154 r180 top locked
C153 "GRM21BR61A476ME15" 0805_HV 2806,1154 r0 top locked
C154 "GRM21BR61A476ME15" 0805_HV 2806,1056 r0 top locked
C155 "GRM21BR60G107ME15L" 0805_HV 3006.37,813.19 r90 top locked
C156 "GRM188R60J475ME19D" 0603 3088.37,810.19 r90 top locked
C157 "GRM188R61A335KE15D" 0603 3055.37,687.19 r180 top locked
C158 "GRM155R60J102KA01D" 0402 3284.37,603.19 r180 top locked
FID1 "Fiducial" Fiducial10-20 600,4250 r90 top locked
FID2 "Fiducial" Fiducial10-20 600,250 r90 bottom locked
FID3 "Fiducial" Fiducial10-20 4900,250 r90 top locked
FID4 "Fiducial" Fiducial10-20 600,4250 r270 bottom locked
FID5 "Fiducial" Fiducial10-20 600,250 r270 top locked
FID6 "Fiducial" Fiducial10-20 4900,250 r270 bottom locked
H1 "SJ-5303 (CLEAR)" Bumpon_SJ5003Transparent 250,250 r180 bottom locked
H2 "SJ-5303 (CLEAR)" Bumpon_SJ5003Transparent 250,4250 r180 bottom locked
H3 "SJ-5303 (CLEAR)" Bumpon_SJ5003Transparent 5250,4250 r180 bottom locked
H4 "SJ-5303 (CLEAR)" Bumpon_SJ5003Transparent 5250,250 r180 bottom locked
J1 "1935776" Phoenix_1935776 3345,4319 r180 top locked
J2 "U.FL-R-SMT-1" CONN_UFL-R-SMT-1 4853.25,903.9 r0 top
J3 "1935776" Phoenix_1935776 5319.33,1251.92 r90 top locked
J4 "1935776" Phoenix_1935776 180,3111 r270 top locked
J5 "U.FL-R-SMT-1" CONN_UFL-R-SMT-1 1020.59,2825.22 r180 top locked
J6 "1935776" Phoenix_1935776 180,2514.15 r270 top locked
J7 "1935776" Phoenix_1935776 180,1917.3 r270 top locked
J8 "1935776" Phoenix_1935776 2887.55,179 r0 top locked
J9 "U.FL-R-SMT-1" CONN_UFL-R-SMT-1 2467.12,3517.72 r90 top locked
J10 "1935776" Phoenix_1935776 2748.15,4319 r180 top locked
J11 "U.FL-R-SMT-1" CONN_UFL-R-SMT-1 1925.57,631.29 r270 top locked
J12 "1935776" Phoenix_1935776 2240.7,179 r0 top locked
J13 "U.FL-R-SMT-1" CONN_UFL-R-SMT-1 4555.25,1749.91 r270 top locked
J14 "1935776" Phoenix_1935776 5319.33,1898.77 r90 top locked
J15 "1935776" Phoenix_1935776 180,723.6 r270 top locked
J16 "1935776" Phoenix_1935776 1554.45,4319 r180 top locked
J17 "1935776" Phoenix_1935776 2151.3,4319 r180 top locked
J18 "1935776" Phoenix_1935776 947,179 r0 top locked
J19 "1935776" Phoenix_1935776 1593.85,179 r0 top locked
J20 "1935776" Phoenix_1935776 4181.25,179 r0 top locked
J21 "N2510-6002-RB" CONN_2510-6002 1101.26,3976.19 r270 top locked
J22 "5103308-1" CONN_5103308-1 4147.51,4217.57 r180 top locked
J23 "1935776" Phoenix_1935776 5319.33,3739.32 r90 top locked
J24 "1935776" Phoenix_1935776 5319.33,3142.47 r90 top locked
J25 "1935776" Phoenix_1935776 5319.33,2545.62 r90 top locked
J26 "U.FL-R-SMT-1" CONN_UFL-R-SMT-1 4976.13,4259.85 r90 top locked
J27 "U.FL-R-SMT-1" CONN_UFL-R-SMT-1 1059.96,1355.78 r180 top
J28 "1935776" Phoenix_1935776 180,1320.45 r270 top locked
J29 "U.FL-R-SMT-1" CONN_UFL-R-SMT-1 3593.43,817.52 r270 top locked
J30 "1935776" Phoenix_1935776 3534.4,179 r0 top locked
L1 "74437368022" WE-LHMI_1040 3194.42,1702.59 r0 top locked
L2 "744325180" WE-HC6 1874.83,2529.22 r180 top locked
L3 "74437368022" WE-LHMI_1040 2287.42,1456.59 r270 top locked
L4 "744325180" WE-HC6 3373.42,2395.59 r0 top locked
L5 "744309047" WE-HCM_1390 4330,3320 r0 top locked
L6 "744777001" WE-PD-M 2012.42,1907.59 r180 top locked
L7 "744777001" WE-PD-M 2677.42,1533.59 r270 top locked
Logo1 "Texas Instruments" TI_Stacked_Overlay_Small 1274.46,1125.99 r0 top locked
Logo2 "Pb-Free Symbol" Pb-Free_Overlay_Small 745.5,1141.86 r0 top locked
Q1 "CSD87331Q3D" TRANS_NexFET_Q3D 3031.21,2026.33 r270 top locked
Q2 "CSD87331Q3D" TRANS_NexFET_Q3D 2059.8,2187.59 r90 top locked
Q3 "CSD87331Q3D" TRANS_NexFET_Q3D 3030.09,2274.71 r0 top locked
R1 "KRL2012E-M-R002-G-T5" 0508 1991.92,1627.76 r90 top locked
R2 "KRL2012E-M-R002-G-T5" 0508 2842.42,1799.59 r90 top locked
R3 "KRL2012E-M-R002-G-T5" 0508 2686.89,2604.59 r0 top locked
R4 "KRL2012E-M-R002-G-T5" 0508 2487.89,1765.59 r0 top locked
R5 "KRL2012E-M-R002-G-T5" 0508 2614.42,1765.59 r180 top locked
R6 "KRL2012E-M-R002-G-T5" 0508 2274.89,1948.59 r0 top locked
R7 "KRL2012E-M-R002-G-T5" 0508 3232.17,2725.68 r180 top locked
R8 "CRCW04020000Z0ED" 0402 3368.04,1968.59 r180 top locked
R9 "CRCW04020000Z0ED" 0402 1729.42,2243.59 r0 top locked
R10 "CRCW0402100KJNED" 0402 182.31,3715.79 r180 top locked
R11 "CRCW0402100KJNED" 0402 446.92,3688.25 r270 top locked
R12 "CRCW04020000Z0ED" 0402 490.86,3688.25 r270 top locked
R13 "CRCW0402100KJNED" 0402 689.84,3712.79 r0 top locked
R14 "CRCW0402100KJNED" 0402 377.93,3715.79 r180 top locked
R15 "CRCW04020000Z0ED" 0402 2473.89,2830.1 r180 top locked
R16 "CRCW0402100KJNED" 0402 279.93,3715.79 r180 top locked
R17 "CRCW0402100KJNED" 0402 826.43,3712.79 r180 top locked
R18 "KRL2012E-M-R002-G-T5" 0508 2383.43,2604.59 r180 top locked
R19 "CRCW04020000Z0ED" 0402 565.93,3688.25 r90 top locked
R20 "CRCW04020000Z0ED" 0402 2870.42,1962.59 r0 top locked
R21 "KRL2012E-M-R002-G-T5" 0508 3374.42,2072.59 r180 top locked
R22 "CRCW04020000Z0ED" 0402 2870.42,2044.59 r0 top locked
R23 "CRCW04020000Z0ED" 0402 2870.42,2003.59 r0 top locked
R24 "CRCW040249R9FKED" 0402 4793.21,1053.89 r270 top
R25 "CRCW04022R20JNED" 0402 3038.04,1453.59 r180 top locked
R26 "CRCW04020000Z0ED" 0402 3555.42,1718.59 r180 bottom locked
R27 "CRCW04027K50FKED" 0402 2762.42,1807.97 r270 top locked
R28 "CRCW04020000Z0ED" 0402 2204.42,2253.59 r180 top locked
R29 "KRL2012E-M-R002-G-T5" 0508 1720.89,2165.59 r0 top locked
R30 "CRCW04020000Z0ED" 0402 2204.42,2167.59 r180 top locked
R31 "CRCW04020000Z0ED" 0402 2204.42,2211.59 r180 top locked
R32 "CRCW04022R20JNED" 0402 2165.22,2610.75 r270 top locked
R33 "CRCW040249R9FKED" 0402 1057.01,2687.51 r0 top locked
R34 "CRCW04020000Z0ED" 0402 1615.04,2645.22 r180 bottom locked
R35 "CRCW04020000Z0ED" 0402 1615.04,2686.22 r180 bottom locked
R36 "CRCW04024K70JNED" 0402 2344.42,2445.22 r90 top locked
R37 "CRCW040249R9FKED" 0402 2635.09,3457.6 r180 top locked
R38 "CRCW040249R9FKED" 0402 2092.23,691.33 r180 top locked
R39 "CRCW04020000Z0ED" 0402 2306.42,1112.59 r90 bottom locked
R40 "CRCW04020000Z0ED" 0402 2722.42,2420.59 r0 bottom locked
R41 "CRCW04020000Z0ED" 0402 2870.42,2211.59 r0 top locked
R42 "KRL2012E-M-R002-G-T5" 0508 2938.42,2618.59 r270 top locked
R43 "CRCW04020000Z0ED" 0402 2870.42,2167.59 r0 top locked
R44 "CRCW04020000Z0ED" 0402 2870.42,2126.59 r0 top locked
R45 "CRCW040249R9FKED" 0402 4555.25,1897.44 r270 top locked
R46 "CRCW04022R20JNED" 0402 3080.48,2608.9 r270 top locked
R47 "CRCW0402267KFKED" 0402 3702.78,2401.91 r180 bottom locked
R48 "CRCW0402133KFKED" 0402 3702.78,2360.47 r0 bottom locked
R49 "CRCW04024K30JNED" 0402 2870.42,2294.59 r0 top locked
R50 "KRL2012E-M-R002-G-T5" 0508 2330.92,1843.07 r90 bottom locked
R51 "CRCW0402100KFKED" 0402 1969.79,2929.26 r90 top locked
R52 "CRCW0402100KFKED" 0402 2181.29,2929.26 r90 top locked
R53 "CRCW0402100KFKED" 0402 2040.29,2929.26 r90 top locked
R54 "CRCW0402100KFKED" 0402 2251.79,2929.26 r90 top locked
R55 "CRCW0402100KFKED" 0402 2110.79,2929.26 r90 top locked
R56 "CRCW04020000Z0ED" 0402 1051.26,3508.47 r90 top locked
R57 "CRCW04020000Z0ED" 0402 1151.26,3508.47 r90 top locked
R58 "CRCW0402100KFKED" 0402 3784.23,2756.38 r90 top locked
R59 "CRCW040211K5FKED" 0402 3705,2916.38 r270 top locked
R60 "CRCW04020000Z0ED" 0402 3792,2916.38 r90 top locked
R61 "CRCW040210K0FKED" 0402 3841.34,2756.38 r270 top locked
R62 "CRCW04020000Z0ED" 0402 3833,2916.38 r270 top locked
R63 "CRCW040210K0FKED" 0402 3642.04,2840.57 r270 top locked
R64 "ERJ-2RKF49R9X" 0402 3642.04,2937.9 r90 top locked
R65 "CRCW040240K2FKED" 0402 3894.23,2926.38 r270 top locked
R66 "CRCW04021K00FKED" 0402 3580.23,2842.38 r90 top locked
R67 "CRCW040234K8FKED" 0402 3984.23,3006.38 r0 top locked
R68 "CRCW040210K0FKED" 0402 3566,3056.92 r0 top locked
R69 "CRCW04028K66FKED" 0402 3984.23,3056.38 r0 top locked
R70 "CRCW040251R0JNED" 0402 5342.68,3166.2 r180 bottom locked
R71 "CRCW04020000Z0ED" 0402 3568.93,3085.81 r0 bottom locked
R72 "CRCW04020000Z0ED" 0402 3972.31,3136.38 r90 top locked
R73 "CRCW040251R0JNED" 0402 5342.42,3119.79 r180 bottom locked
R74 "CRCW040249R9FKED" 0402 4976.13,4108.98 r90 top locked
R75 "CRCW12061R00JNEA" 1206 3864.23,3451.38 r90 top locked
R76 "RT0603DRE0710KL" 0603 1158.14,1627.17 r0 top
R77 "RT0603DRE072K49L" 0603 970.26,1511.84 r90 top locked
R78 "CRCW040249R9FKED" 0402 1124.91,1508.45 r270 top
R79 "RT0603DRE074K99L" 0603 915.26,1511.84 r90 top locked
R80 "CRCW04020000Z0ED" 0402 1766.22,1903.59 r0 bottom locked
R81 "RT0603DRE0710KL" 0603 3317.12,938.43 r90 top
R82 "CRCW040249R9FKED" 0402 3452.49,911.87 r0 top
R83 "RT0603DRE07619KL" 0603 3440.37,753.49 r180 top locked
R84 "RT0603DRE074K99L" 0603 3440.37,698.49 r180 top locked
R85 "CRCW04020000Z0ED" 0402 2693.42,1284.59 r90 bottom locked
S1 "SDA06H1SBD" SW_SDA06H1SBD 515.93,3965.79 r0 top locked
TP1 "5000" Keystone5000 3092.71,4003.5 r180 top locked
TP2 "5001" Keystone5001 3604.7,4003.5 r180 top locked
TP3 "5015" Testpoint_Keystone_Miniature 261.14,306.07 r180 top locked
TP4 "5015" Testpoint_Keystone_Miniature 4842.15,397.77 r180 top locked
TP5 "5015" Testpoint_Keystone_Miniature 262.93,4318.79 r180 top locked
TP6 "5015" Testpoint_Keystone_Miniature 179.93,3499.79 r90 top locked
TP7 "5015" Testpoint_Keystone_Miniature 562.13,3499.79 r90 top locked
TP8 "5015" Testpoint_Keystone_Miniature 689.53,3499.79 r90 top locked
TP9 "5015" Testpoint_Keystone_Miniature 434.73,3499.79 r90 top locked
TP10 "5015" Testpoint_Keystone_Miniature 2499.42,2956.59 r90 top locked
TP11 "5015" Testpoint_Keystone_Miniature 2780.42,2956.59 r270 top locked
TP12 "5015" Testpoint_Keystone_Miniature 307.33,3499.79 r90 top locked
TP13 "5015" Testpoint_Keystone_Miniature 3538.65,2043.91 r270 top locked
TP14 "5015" Testpoint_Keystone_Miniature 816.93,3499.79 r90 top locked
TP15 "5015" Testpoint_Keystone_Miniature 2639.42,2956.59 r90 top locked
TP16 "5015" Testpoint_Keystone_Miniature 2359.42,2956.59 r90 top locked
TP17 "5000" Keystone5000 5019.33,1420.34 r180 top locked
TP18 "5001" Keystone5001 5019.33,1083.49 r180 top locked
TP19 "5000" Keystone5000 480,2345.72 r90 top locked
TP20 "5001" Keystone5001 480,2682.57 r90 top locked
TP21 "5000" Keystone5000 2409.13,479 r0 top locked
TP22 "5001" Keystone5001 2072.28,479 r0 top locked
TP23 "5000" Keystone5000 2579.72,4019 r270 top locked
TP24 "5001" Keystone5001 2916.57,4019 r270 top locked
TP25 "5000" Keystone5000 5019.33,2067.19 r90 top locked
TP26 "5001" Keystone5001 5019.33,1730.34 r90 top locked
TP27 "5000" Keystone5000 480,555.17 r180 top locked
TP28 "5000" Keystone5000 1386.02,4019 r0 top locked
TP29 "5000" Keystone5000 1982.87,4019 r0 top locked
TP30 "5001" Keystone5001 480,892.02 r180 top locked
TP31 "5001" Keystone5001 2319.72,4019 r0 top locked
TP32 "5001" Keystone5001 1722.87,4019 r0 top locked
TP33 "5000" Keystone5000 1115.43,479 r270 top locked
TP34 "5000" Keystone5000 1762.28,479 r180 top locked
TP35 "5000" Keystone5000 4349.68,479 r180 top locked
TP36 "5001" Keystone5001 778.58,479 r0 top locked
TP37 "5001" Keystone5001 1425.43,479 r270 top locked
TP38 "5001" Keystone5001 4012.83,479 r180 top locked
TP39 "5000" Keystone5000 3944.03,2780 r180 top locked
TP40 "5000" Keystone5000 3421,2866 r180 top locked
TP41 "5000" Keystone5000 3421,3029.52 r180 top locked
TP42 "5000" Keystone5000 3420,3190.52 r180 top locked
TP43 "5000" Keystone5000 3420,3333.24 r180 top locked
TP44 "5000" Keystone5000 5191.13,3436.89 r180 top locked
TP45 "5000" Keystone5000 3420,3475.97 r180 top locked
TP46 "5000" Keystone5000 3975,3610 r180 top locked
TP47 "5000" Keystone5000 5384.39,3436.89 r90 top locked
TP48 "5001" Keystone5001 5320.09,2867.18 r90 top locked
TP49 "5000" Keystone5000 480,1152.02 r270 top locked
TP50 "5001" Keystone5001 480,1488.87 r270 top locked
TP51 "5000" Keystone5000 3702.83,479 r0 top locked
TP52 "5001" Keystone5001 3365.98,479 r0 top locked
U1 "TPS650864A0RSKR" RSK0064C 2551.99,2122.47 r0 top locked
U2 "TPS544C25RVF" RVF0040A 3791.47,3156.38 r180 top locked
U3 "TPS74901RGWT" RGW0020A 968.96,1704.24 r180 top locked
U4 "TPS74901RGWT" RGW0020A 3248.17,752.19 r270 top locked
ZZ1 "These assemblies are ESD sensitive, ESD precautions shall be observed." AssemblyNote 290.51,4869.43 r0 top locked
ZZ2 "These assemblies must be clean and free from flux and all contaminants. Use of no clean flux is not acceptable." AssemblyNote 291.43,4764.93 r0 top locked
ZZ3 "These assemblies must comply with workmanship standards IPC-A-610 Class 2, unless otherwise specified." AssemblyNote 293.06,4655.27 r0 top locked

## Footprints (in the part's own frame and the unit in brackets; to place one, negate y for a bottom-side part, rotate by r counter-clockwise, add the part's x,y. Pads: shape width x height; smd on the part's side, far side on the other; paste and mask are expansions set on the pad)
0402 [mm] "0402 from SM-752 data"
  rect 0.8x0.6 smd: 1(-0.6,0) 2(0.6,0)
  silkscreen extent -1.22,-0.52 1.22,0.52, body extent -0.55,-0.3 0.55,0.3, height 0.6
0402L [mm] "0402 from SM-752 data"
  rect 0.6x0.5 smd: 1(-0.5,0) 2(0.5,0)
  body extent -0.55,-0.3 0.55,0.3, height 0.6
0508 [mm] "IPC nominal based on TDK C1220 type capacitors e4162_c.pdf"
  rect 0.8x2.25 smd: 1(-0.75,0) 2(0.75,0)
  silkscreen extent -1.44,-1.42 1.44,1.42, body extent -0.72,-1.1 0.72,1.1, height 1
0603 [mm] "0603 from SM-752 data"
  rect 1x0.95 smd: 1(-0.8,0) 2(0.8,0)
  silkscreen extent -1.52,-0.69 1.52,0.69, body extent -0.87,-0.47 0.87,0.47, height 1
0603_120 [mm] "0603_120"
  rect 1x1 smd: 1(-0.8,0) 2(0.8,0)
  silkscreen extent -0.1,-0.58 0.1,0.58, body extent -0.87,-0.48 0.87,0.48, height 1.2
0603L [mm] "0603 from SM-752 data"
  rect 0.8x0.85 smd: 1(-0.7,0) 2(0.7,0)
  silkscreen extent -0.07,-0.33 0.07,0.33, body extent -0.87,-0.47 0.87,0.47, height 1
0805_HV [mil] "0805 with 30mil clearance between pads"
  rect 50x63 smd: 1(-40,0) 2(40,0)
  silkscreen extent -74,-40 74,40, body extent -43,-29 43,29, height 57
1206 [mm] "1206 from SM-752 data"
  rect 1.3x1.85 smd: 1(-1.45,0) 2(1.45,0)
  silkscreen extent -2.4,-1.21 2.4,1.21, body extent -1.7,-0.9 1.7,0.9, height 1.35
1210 [mm] "1210 from SM-752 data"
  rect 1.3x2.7 smd: 1(-1.45,0) 2(1.45,0)
  silkscreen extent -2.32,-1.57 2.32,1.57, body extent -1.7,-1.35 1.7,1.35, height 1.35
7343-43 [mm] "Medium density IPC based on Kemet T495 series"
  rect 2.55x2.45 smd: 1(-3.025,0) 2(3.025,0)
  silkscreen extent -4.56,-2.3 3.8,2.3, body extent -3.8,-2.3 3.8,2.3, height 4.3
AssemblyNote [mil] "Assembly Note"
Bumpon_SJ5003Transparent [mil] "3M Hemispherical Bumpon transparent"
  round 1 on Mech4: 0(0,0)
  silkscreen extent -228,-228 228,228, body extent -219,-218 219,218, height 197
CONN_2510-6002 [mm] "3M 2500 series TS-0770-L December 15, 2011"
  rect 1.65x1.65 hole 1.016: 1(-5.08,-1.27)
  round 1.65 hole 1.016: 2(-5.08,1.27) 3(-2.54,-1.27) 4(-2.54,1.27) 5(0,-1.27) 6(0,1.27) 7(2.54,-1.27) 8(2.54,1.27) 9(5.08,-1.27) 10(5.08,1.27)
  silkscreen extent -10.01,-4.17 10.01,4.47, body extent -10.01,-4.11 10.01,4.52, height 9.92
CONN_5103308-1 [mm] "TE Connectivity (AMP) Rev E datasheet"
  rect 1.65x1.65 hole 1.016: 1(-5.08,-1.27)
  round 1.65 hole 1.016: 2(-5.08,1.27) 3(-2.54,-1.27) 4(-2.54,1.27) 5(0,-1.27) 6(0,1.27) 7(2.54,-1.27) 8(2.54,1.27) 9(5.08,-1.27) 10(5.08,1.27)
  silkscreen extent -10.16,-4.57 10.16,4.57, body extent -10.16,-4.57 10.16,4.57, height 9.87
CONN_UFL-R-SMT-1 [mm] "Hirose recommended land pattern http://www.hirose.co.jp/cataloge_hp/e32119372.pdf 2009.2"
  rect 1.05x1 smd: 1(-1.525,0)
  rect 2.2x1.05 smd: 2(0,1.475) 3(0,-1.475)
  Top Layer keep-out region: -0.8,-0.7 1.1,-0.7 1.1,0.7 -0.8,0.7
  silkscreen extent -1.7,-1.7 1.7,1.7, body extent -1.55,-1.5 1.55,1.5, height 1.27
Fiducial10-20 [mm]
  round 1 smd mask+0.5: 1(0,0)
  Top Layer keep-out circle w1.178: c0,0 r0.5
Keystone5000 [mil] "For Keystone 500x miniature loop terminals"
  round 80 hole 40: 1(0,0)
  silkscreen extent -58,-58 58,58, body extent -49,-49 49,49, height 182
Keystone5001 [mil] "For Keystone 500x miniature loop terminals"
  round 80 hole 40: 1(0,0)
  silkscreen extent -58,-58 58,58, body extent -49,-49 49,49, height 182
Pb-Free_Overlay_Small [mil]
  silkscreen extent -46,-46 46,46
Phoenix_1935776 [mm] "Terminal Block, 2x1, 5mm, TH"
  rect 1.8x1.8 hole 1.3: 1(-2.5,0)
  round 1.8 hole 1.3: 2(2.5,0)
  silkscreen extent -5.3,-4.5 5,4.5, body extent -5,-4.5 5,4.5, height 13.5
RGW0020A [mm] "QFN, 20-Leads, Body 5x5mm, Pitch 0.65mm, Thermal Pad 3.15x3.15mm, TI Recommended"
  oval 0.75x0.3 smd: 1(-2.325,1.3) 2(-2.325,0.65) 3(-2.325,0) 4(-2.325,-0.65) 5(-2.325,-1.3) 11(2.325,-1.3) 12(2.325,-0.65) 13(2.325,0) 14(2.325,0.65) 15(2.325,1.3)
  oval 0.3x0.75 smd: 6(-1.3,-2.325) 7(-0.65,-2.325) 8(0,-2.325) 9(0.65,-2.325) 10(1.3,-2.325) 16(1.3,2.325) 17(0.65,2.325) 18(0,2.325) 19(-0.65,2.325) 20(-1.3,2.325)
  rect 3.15x3.15 smd paste-1.575: 21(0,0)
  silkscreen extent -2.73,-2.73 2.73,2.73, body extent -2.58,-2.57 2.57,2.58, height 1.01
RSK0064C [mm] "QFN, 64-Leads, Body 8x8mm, Pitch 0.4mm"
  oval 0.7x0.2 smd: 1(-3.85,3) 2(-3.85,2.6) 3(-3.85,2.2) 4(-3.85,1.8) 5(-3.85,1.4) 6(-3.85,1) 7(-3.85,0.6) 8(-3.85,0.2) 9(-3.85,-0.2) 10(-3.85,-0.6) 11(-3.85,-1) 12(-3.85,-1.4) 13(-3.85,-1.8) 14(-3.85,-2.2) 15(-3.85,-2.6) 16(-3.85,-3) 33(3.85,-3) 34(3.85,-2.6) 35(3.85,-2.2) 36(3.85,-1.8) 37(3.85,-1.4) 38(3.85,-1) 39(3.85,-0.6) 40(3.85,-0.2) 41(3.85,0.2) 42(3.85,0.6) 43(3.85,1) 44(3.85,1.4) 45(3.85,1.8) 46(3.85,2.2) 47(3.85,2.6) 48(3.85,3)
  oval 0.2x0.7 smd: 17(-3,-3.85) 18(-2.6,-3.85) 19(-2.2,-3.85) 20(-1.8,-3.85) 21(-1.4,-3.85) 22(-1,-3.85) 23(-0.6,-3.85) 24(-0.2,-3.85) 25(0.2,-3.85) 26(0.6,-3.85) 27(1,-3.85) 28(1.4,-3.85) 29(1.8,-3.85) 30(2.2,-3.85) 31(2.6,-3.85) 32(3,-3.85) 49(3,3.85) 50(2.6,3.85) 51(2.2,3.85) 52(1.8,3.85) 53(1.4,3.85) 54(1,3.85) 55(0.6,3.85) 56(0.2,3.85) 57(-0.2,3.85) 58(-0.6,3.85) 59(-1,3.85) 60(-1.4,3.85) 61(-1.8,3.85) 62(-2.2,3.85) 63(-2.6,3.85) 64(-3,3.85)
  rect 5.7x5.7 smd paste-5.7: 65(0,0)
  silkscreen extent -4.18,-4.18 4.18,4.18, body extent -4.08,-4.08 4.08,4.08, height 1.01
RVF0040A [mm]
  oval 0.6x0.24 smd: 1(-2.4,2.75) 2(-2.4,2.25) 3(-2.4,1.75) 4(-2.4,1.25) 5(-2.4,0.75) 6(-2.4,0.25) 7(-2.4,-0.25) 8(-2.4,-0.75) 9(-2.4,-1.25) 10(-2.4,-1.75) 11(-2.4,-2.25) 12(-2.4,-2.75) 21(2.4,-2.75) 22(2.4,-2.25) 23(2.4,-1.75) 24(2.4,-1.25) 25(2.4,-0.75) 26(2.4,-0.25) 27(2.4,0.25) 28(2.4,0.75) 29(2.4,1.25) 30(2.4,1.75) 31(2.4,2.25) 32(2.4,2.75)
  oval 0.24x0.6 smd: 13(-1.75,-3.4) 14(-1.25,-3.4) 15(-0.75,-3.4) 16(-0.25,-3.4) 17(0.25,-3.4) 18(0.75,-3.4) 19(1.25,-3.4) 20(1.75,-3.4) 33(1.75,3.4) 34(1.25,3.4) 35(0.75,3.4) 36(0.25,3.4) 37(-0.25,3.4) 38(-0.75,3.4) 39(-1.25,3.4) 40(-1.75,3.4)
  rect 3.3x5.3 smd paste-2: 41(0,0)
  silkscreen extent -2.7,-3.7 2.7,3.7, body extent -2.57,-3.57 2.57,3.57, height 1.52
SM_RADIAL_10AMM [mm] "10 x 7.9mm:  Sanyo Oscon F8"
  rect 4.4x1.9 smd: 1(-4.35,0) 2(4.35,0)
  silkscreen extent -5.25,-5.25 5.25,5.25, body extent -5.25,-5.25 5.25,5.25, height 8
SP-Cap_Standard [mm] "Recommended land pattern for standard Panasonic SP-CAP capacitors"
  rect 2.4x2.8 smd: 1(-3.2,0) 2(3.2,0)
  silkscreen extent -4.25,-2.34 3.75,2.34, body extent -3.75,-2.25 3.75,2.25, height 2.11
SW_SDA06H1SBD [mil] "Swittch SPST 6 Pos."
  rect 59x85 smd: 1(-250,-162) 2(-150,-162) 3(-50,-162) 4(50,-162) 5(150,-162) 6(250,-162) 7(250,162) 8(150,162) 9(50,162) 10(-50,162) 11(-150,162) 12(-250,162)
  body extent -340,-150 340,150, height 197
Testpoint_Keystone_Miniature [mil] "Miniature SMT test point"
  rect 135x70 smd: 1(0,0)
  silkscreen extent -78,-46 78,45, body extent -52,-20 52,20, height 61
TI_Stacked_Overlay_Small [mil]
  silkscreen extent -418,-98 418,98
TRANS_NexFET_Q3D [mm] "TI recommended land pattern M0143-01"
  rect 0.65x0.44 smd paste-0.05 mask+0.06: 1(-1.48,0.975) 2(-1.48,0.325) 3(-1.48,-0.325) 4(-1.48,-0.975) 5(1.48,-0.975) 6(1.48,-0.325) 7(1.48,0.325) 8(1.48,0.975)
  rect 1.9x2.8 smd paste-5 mask+0.06: 9(0,0)
  Top Layer region: -0.74,-1.75 -0.44,-1.75 -0.44,-1.4 -0.74,-1.4
  Top Layer region: 0.44,-1.75 0.74,-1.75 0.74,-1.4 0.44,-1.4
  Top Layer region: -0.74,1.4 -0.44,1.4 -0.44,1.75 -0.74,1.75
  Top Layer region: 0.44,1.4 0.74,1.4 0.74,1.75 0.44,1.75
  Top Layer region: -1.805,0.531 -1.155,0.531 -1.155,0.76 -1.805,0.76
  silkscreen extent -2.05,-2 2,2, body extent -1.7,-1.7 1.7,1.7, height 1.42
WE-HC6 [mm] "Wurth Electronik recommended land pattern"
  rect 3.85x4 smd: 1(-3.825,0) 2(3.825,0)
  silkscreen extent -6.2,-6.2 6.2,6.2, body extent -5.76,-5.36 5.74,5.34, height 5
WE-HCM_1390 [mm] "SMD, Body 12.5x13mm"
  rect 2.5x5 smd: 1(-6.25,0) 2(6.25,0)
  silkscreen extent -6.5,-6.75 6.5,6.75, body extent -6.5,-6.75 6.5,6.75, height 9.5
WE-LHMI_1040 [mm] "Wurth"
  rect 4.1x3.5 smd: 1(-4.75,0) 2(4.75,0)
  silkscreen extent -5.5,-5.15 5.5,5.15, body extent -5.5,-5.15 5.5,5.15, height 4
WE-PD-M [mm] "Wurth Elektronik recommended land pattern, 2008-01-04"
  rect 2x1.7 smd: 1(-3,0) 2(3,0)
  silkscreen extent -4.3,-4 4.3,4, body extent -3.8,-3.82 3.8,3.77, height 4.5

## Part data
C1: "CAP, TA, 47 µF, 35 V, +/- 10%, 0.3 ohm, SMD"
C2 C3: "CAP, CERM, 2.2 µF, 6.3 V, +/- 10%, X5R, 0402"
C4 C5 C6 C7: "CAP, CERM, 10 µF, 10 V, +/- 20%, X5R, 0402"
C8 C88 C89 C90: "CAP, CERM, 4.7 µF, 6.3 V, +/- 20%, X5R, 0402"
C9 C10 C15: "CAP, CERM, 1 µF, 10 V, +/- 10%, X5R, 0402"
C11: "CAP, CERM, 1 µF, 35 V, +/- 10%, X5R, 0402"
C12 C18 C24 C25 C31 C44 C45 C60 C69 C70 C71 C80 C91 C92 C93 C136 C151: "CAP, CERM, 0.1 µF, 10 V, +/- 10%, X5R, 0402"
C13 C14: "CAP, CERM, 4.7 µF, 10 V, +/- 20%, X5R, 0603"
C16 C17 C32 C33 C72 C73: "CAP, CERM, 22 µF, 25 V, +/- 20%, X5R, 0805"
C19 C20 C21 C22 C23 C38 C39 C40 C41 C42 C43 C56 C57 C58 C59 C67 C68 C74 C75 C76 C77 C133 C134 C135 C148 C149 C150: "CAP, CERM, 22 µF, 6.3 V, +/- 20%, X5R, 0603"
C26 C27 C28 C46 C47 C48 C61 C62 C63 C81 C82 C83 C127 C128 C129 C137 C138 C139 C152 C153 C154: "CAP, CERM, 47 µF, 10 V, +/- 20%, X5R, 0805"
C29 C49 C55 C64 C86 C130 C142 C147: "CAP, CERM, 0.1 µF, 25 V, +/- 10%, X5R, 0402"
C30 C50 C87: "CAP, CERM, 6800 pF, 25 V, +/- 10%, X7R, 0402"
C34 C36 C51 C53 C65 C84 C98 C102 C140 C155: "CAP, CERM, 100 µF, 4 V, +/- 20%, X5R, 0805"
C35 C37 C52 C54 C66 C85 C99 C103 C141 C156: "CAP, CERM, 4.7 µF, 6.3 V, +/- 20%, X5R, 0603"
C78 C79: "CAP, CERM, 47 µF, 4 V, +/- 20%, X5R, 0603"
C94: "CAP, CERM, 100 pF, 50 V, +/- 5%, C0G/NP0, 0402"
C95: "CAP, CERM, 2200 pF, 50 V, +/- 10%, X7R, 0402"
C96: "CAP, CERM, 2700 pF, 50 V, +/- 10%, X7R, 0402"
C97 C101: "CAP, Aluminum Polymer, 680 µF, 4 V, +/- 20%, 0.025 ohm, 10x10.3 SMD"
C100: "CAP, CERM, 330 pF, 50 V, +/- 10%, X7R, 0402"
C104: "CAP, CERM, 1uF, 25V, +/-10%, X7R, 0603"
C105: "CAP, CERM, 47 µF, 6.3 V, +/- 20%, X5R, 0603"
C106: "CAP, CERM, 4.7 µF, 6.3 V, +/- 10%, X5R, 0603"
C107: "CAP, CERM, 4.7 µF, 10 V, +/- 20%, X6S, 0603"
C108: "CAP, CERM, 2.2 µF, 6.3 V, +/- 10%, X6S, 0402"
C109: "CAP, CERM, 0.1 µF, 50 V, +/- 20%, X7R, 0402"
C110: "CAP, CERM, 1000pF, 100V, +/-5%, X7R, 0603"
C111: library part EEFSX0E471ER, "CAP, Aluminum Polymer, 470 µF, 2.5 V, +/- 20%, 9 ohm, 7.3x1.8x4.3mm SMD"
C112 C113 C114 C115: "CAP, CERM, 22uF, 25V, +/-10%, X6S, 1210"
C116 C117: "CAP, CERM, 6800pF, 25V, +/-10%, X7R, 0402"
C118 C119 C120 C121 C122 C123 C124: "CAP, CERM, 100 µF, 6.3 V, +/- 20%, X6S, 1210"
C125 C126: "CAP, CERM, 22 µF, 4 V, +/- 20%, X6S, 0805"
C131 C132 C143 C145 C146 C157: "CAP, CERM, 3.3 µF, 10 V, +/- 10%, X5R, 0603"
C144 C158: "CAP, CERM, 1000 pF, 6.3 V, +/- 10%, X5R, 0402"
FID1 FID2 FID3 FID4 FID5 FID6: "Fiducial mark.  There is nothing to buy or mount."
H1 H2 H3 H4: "Bumpon, Hemisphere, 0.44 X 0.20, Clear"
J1 J3 J4 J6 J7 J8 J10 J12 J14 J15 J16 J17 J18 J19 J20 J23 J24 J25 J28 J30: "Terminal Block, 2x1, 5mm, Green, TH"
J2 J5 J9 J11 J13 J26 J27 J29: "Connector, Ultra-Mini Coaxial, SMD"
J21: "Header (shrouded), 100mil, 5x2, High-Temperature, Gold, TH"
J22: "Header (shrouded), 100mil, 5x2, Gold, TH"
L1 L3: "Inductor, Shielded Drum Core, Powdered Iron, 2.2 µH, 10 A, 0.0065 ohm, SMD"
L2 L4: "Inductor, Shielded Drum Core, Superflux, 1.8 µH, 16 A, 0.0035 ohm, SMD"
L5: "Inductor, Shielded Drum Core, Ferrite, 470 nH, 40.5 A, 0.000165 ohm, SMD"
L6 L7: "Inductor, Shielded Drum Core, Metal Composite, 1 µH, 8 A, 0.0084 ohm, SMD"
Logo1: library part TI_Logo, "Texas Instrument Corporate Signature"
Logo2: library part Pb-Free
Q1 Q2 Q3: "MOSFET, N-CH, 30 V, 15 A, 3.4x1.4x3.4mm"
R1 R2 R3 R4 R5 R6 R7 R18 R21 R29 R42 R50: "RES, 0.002, 2%, 1 W, 0508"
R8 R9 R12 R15 R19 R20 R22 R23 R26 R28 R30 R31 R34 R35 R39 R40 R41 R43 R44 R56 R57 R60 R62 R71 R72 R80 R85: "RES, 0, 5%, 0.063 W, 0402"
R10 R11 R13 R14 R16 R17: "RES, 100 k, 5%, 0.063 W, 0402"
R24 R33 R37 R38 R45 R74 R78 R82: "RES, 49.9, 1%, 0.063 W, 0402"
R25 R32 R46: "RES, 2.2, 5%, 0.063 W, 0402"
R27: "RES, 7.50 k, 1%, 0.063 W, 0402"
R36: "RES, 4.7 k, 5%, 0.063 W, 0402"
R47: "RES, 267 k, 1%, 0.063 W, 0402"
R48: "RES, 133 k, 1%, 0.063 W, 0402"
R49: "RES, 4.3 k, 5%, 0.063 W, 0402"
R51 R52 R53 R54 R55 R58: "RES, 100 k, 1%, 0.063 W, 0402"
R59: "RES, 11.5 k, 1%, 0.063 W, 0402"
R61 R63 R68: "RES, 10.0 k, 1%, 0.063 W, 0402"
R64: "RES, 49.9, 1%, 0.1 W, AEC-Q200 Grade 0, 0402"
R65: "RES, 40.2 k, 1%, 0.063 W, 0402"
R66: "RES, 1.00 k, 1%, 0.063 W, 0402"
R67: "RES, 34.8 k, 1%, 0.063 W, 0402"
R69: "RES, 8.66 k, 1%, 0.063 W, 0402"
R70 R73: "RES, 51, 5%, 0.063 W, 0402"
R75: "RES, 1.0 ohm, 5%, 0.25W, 1206"
R76 R81: "RES, 10.0 k, 0.5%, 0.1 W, 0603"
R77: "RES, 2.49 k, 0.5%, 0.1 W, 0603"
R79 R84: "RES, 4.99 k, 0.5%, 0.1 W, 0603"
R83: "RES, 619 k, 0.5%, 0.1 W, 0603"
S1: "Switch, SPST 6Pos, SMT"
TP1 TP17 TP19 TP21 TP23 TP25 TP27 TP28 TP29 TP33 TP34 TP35 TP39 TP40 TP41 TP42 TP43 TP44 TP45 TP46 TP47 TP49 TP51: "Test Point, Miniature, Red, TH"
TP2 TP18 TP20 TP22 TP24 TP26 TP30 TP31 TP32 TP36 TP37 TP38 TP48 TP50 TP52: "Test Point, Miniature, Black, TH"
TP3 TP4 TP5 TP6 TP7 TP8 TP9 TP10 TP11 TP12 TP13 TP14 TP15 TP16: "Test Point, Miniature, SMT"
U1: library part TPS650860A0RSKR, "Simple, Small, and Low-Cost PMU for Intel’s Braswell Platform, RSK0064C"
U2: library part TPS544C24RVF, "18V, 30A PMBUS SYNCHRONOUS BUCK CONVERTERS, RVF0040A"
U3 U4: "Single Output LDO, 3 A, Adjustable 0.8 to 3.6 V Output, 0.8 to 5.5 V Input, with Programmable Soft Start, 20-pin VQFN (RGW), -40 to 125 degC, Green (RoHS & no Sb/Br)"
ZZ1 ZZ2 ZZ3: library part AssemblyNote

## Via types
v1: diameter 18, hole 8, Top Layer to Bottom Layer, tented both sides, 835 vias
v2: diameter 19.68, hole 8.01, Top Layer to Bottom Layer, tented bottom, 42 vias
v3: diameter 18, hole 8.01, Top Layer to Bottom Layer, tented bottom, 27 vias

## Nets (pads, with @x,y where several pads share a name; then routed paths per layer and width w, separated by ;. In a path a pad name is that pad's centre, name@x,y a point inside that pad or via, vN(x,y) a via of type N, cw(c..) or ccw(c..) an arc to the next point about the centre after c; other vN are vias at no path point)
BOOT1: R20.1 U1.35 | length 184
  Top Layer w8: U1.35@2703.57,2035.85 2721.87,2035.85 2724.13,2038.11 2754.59,2038.11 v1(2772.59,2020.11)
  Top Layer w12: v1(2815.5,1962.59) R20.1@2846.8,1962.59
  Signal Layer 1 w6: v1(2772.59,2020.11) 2772.59,2005.5 v1(2815.5,1962.59)
BOOT2: R28.1 U1.5 | length 203.9
  Top Layer w8: R28.1@2228.04,2253.59 2266.49,2253.59 2342.5,2177.59 U1.5@2400.42,2177.59
BOOT6: R41.1 U1.41 | length 210.5
  Top Layer w8: U1.41@2703.57,2130.34 2724.06,2130.34 2726.81,2133.09 2747.29,2133.09 2759.53,2145.34 v1(2806.7,2145.34)
  Top Layer w12: v1(2815.5,2211.59) R41.1@2846.8,2211.59
  Bottom Layer w6: v1(2806.7,2145.34) 2815.5,2154.14 v1(2815.5,2211.59)
BP3: C108.1 R58.1 R61.2 R68.1 U2.27 | length 1284.6
  Top Layer w10: v1(3513.27,3056.92) R68.1@3542.38,3056.92 ; C108.1@3592.97,3232.68 3646.05,3179.6 3646.05,3162.5 3662.01,3146.54 U2.27@3696.98,3146.54 ; v1(3755.11,2732.76) R58.1@3784.23,2732.76 R61.2@3841.34,2732.76
  Signal Layer 1 w10: v1(3625.7,3200.71) 3520.07,3200.71 3471.28,3249.51 3394.34,3249.51 3355.65,3210.81 3355.65,3160 3409.02,3106.64 3463.55,3106.64 v1(3513.27,3056.92) 3513.27,2910.03 3588.73,2834.57 3653.3,2834.57 v1(3755.11,2732.76)
BUCK1_OUT: C19.1 C20.1 C21.1 C22.1 C23.1 C24.1 C25.1 C26.1 C27.1 C28.1 C29.1 J3.2 L1.2 R2.1 R4.1 R5.1 R6.1 R18.2 R24.1 R26.2 TP17.1 | length 1923.2
  Signal Layer 1 w10: v1(3492.99,1718.59) 3492.99,1662.19 3513.52,1641.66 4280.37,1641.66 4653.92,1268.11 4995.79,1268.11 5019.33,1291.65 TP17.1@5019.33,1420.34
  Bottom Layer w12: v1(3492.99,1718.59) R26.2@3531.8,1718.59
  other v1: 2467.49,1712.19 2634.82,1712.19 2432.96,1727.59 2669.35,1727.59 2804.42,1744.66 2842.42,1744.66 2880.42,1744.66 2432.96,1765.59 2669.35,1765.59 2895.82,1779.19 2432.96,1803.59 2669.35,1803.59 2194.55,1910.59 2219.96,1910.59 2194.55,1948.59 2219.96,1948.59 2194.55,1986.59 2219.96,1986.59 2328.49,2566.59 2328.49,2604.59 2328.49,2642.59 2363.03,2658
BUCK2_OUT: C34.1 C35.1 C36.1 C37.1 C38.1 C39.1 C40.1 C41.1 C42.1 C43.1 C44.1 C45.1 C46.1 C47.1 C48.1 C49.1 C51.1 C52.1 J4.2 J6.2 J7.2 L2.2 R33.1 R34.2 TP19.1 | length 1532.7
  Signal Layer 1 w10: TP19.1@480,2345.72 480,2487.75 502.11,2509.86 840.81,2509.86 948.29,2617.33 1591.28,2617.33 1609.7,2598.91 v1(1609.7,2526)
  Bottom Layer w12: R34.2@1591.42,2645.22 1591.42,2601.75 1609.7,2583.47 v1(1609.7,2526)
  other v1: 1145.32,2454.83 1184.68,2463.89 1145.32,2494.68 1184.68,2503.73 1232.73,2504.2 1272.57,2504.2 1312.41,2504.2 1352.25,2504.2 1392.09,2504.2 1431.93,2504.2 1471.78,2504.2 1511.62,2504.2 1551.46,2504.2 1145.32,2534.64 1184.68,2543.57 1223.68,2543.57 1263.52,2543.57 1303.36,2543.57 1343.2,2543.57 1383.17,2543.57 1423.14,2543.57 1463.11,2543.57 1503.08,2543.57 1543.04,2543.57 1583.01,2543.57 1145.32,2574.61 1184.68,2583.41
